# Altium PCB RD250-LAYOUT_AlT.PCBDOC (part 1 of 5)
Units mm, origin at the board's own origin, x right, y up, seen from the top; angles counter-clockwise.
Board outline 318.5 x 135 mm, 6 copper layers (TOP, Mid-Layer 1, Mid-Layer 2, Mid-Layer 3, Mid-Layer 4, BOTTOM), stack 1.422 mm thick; 550 components, 251 nets, 1350 pads, 626 vias.
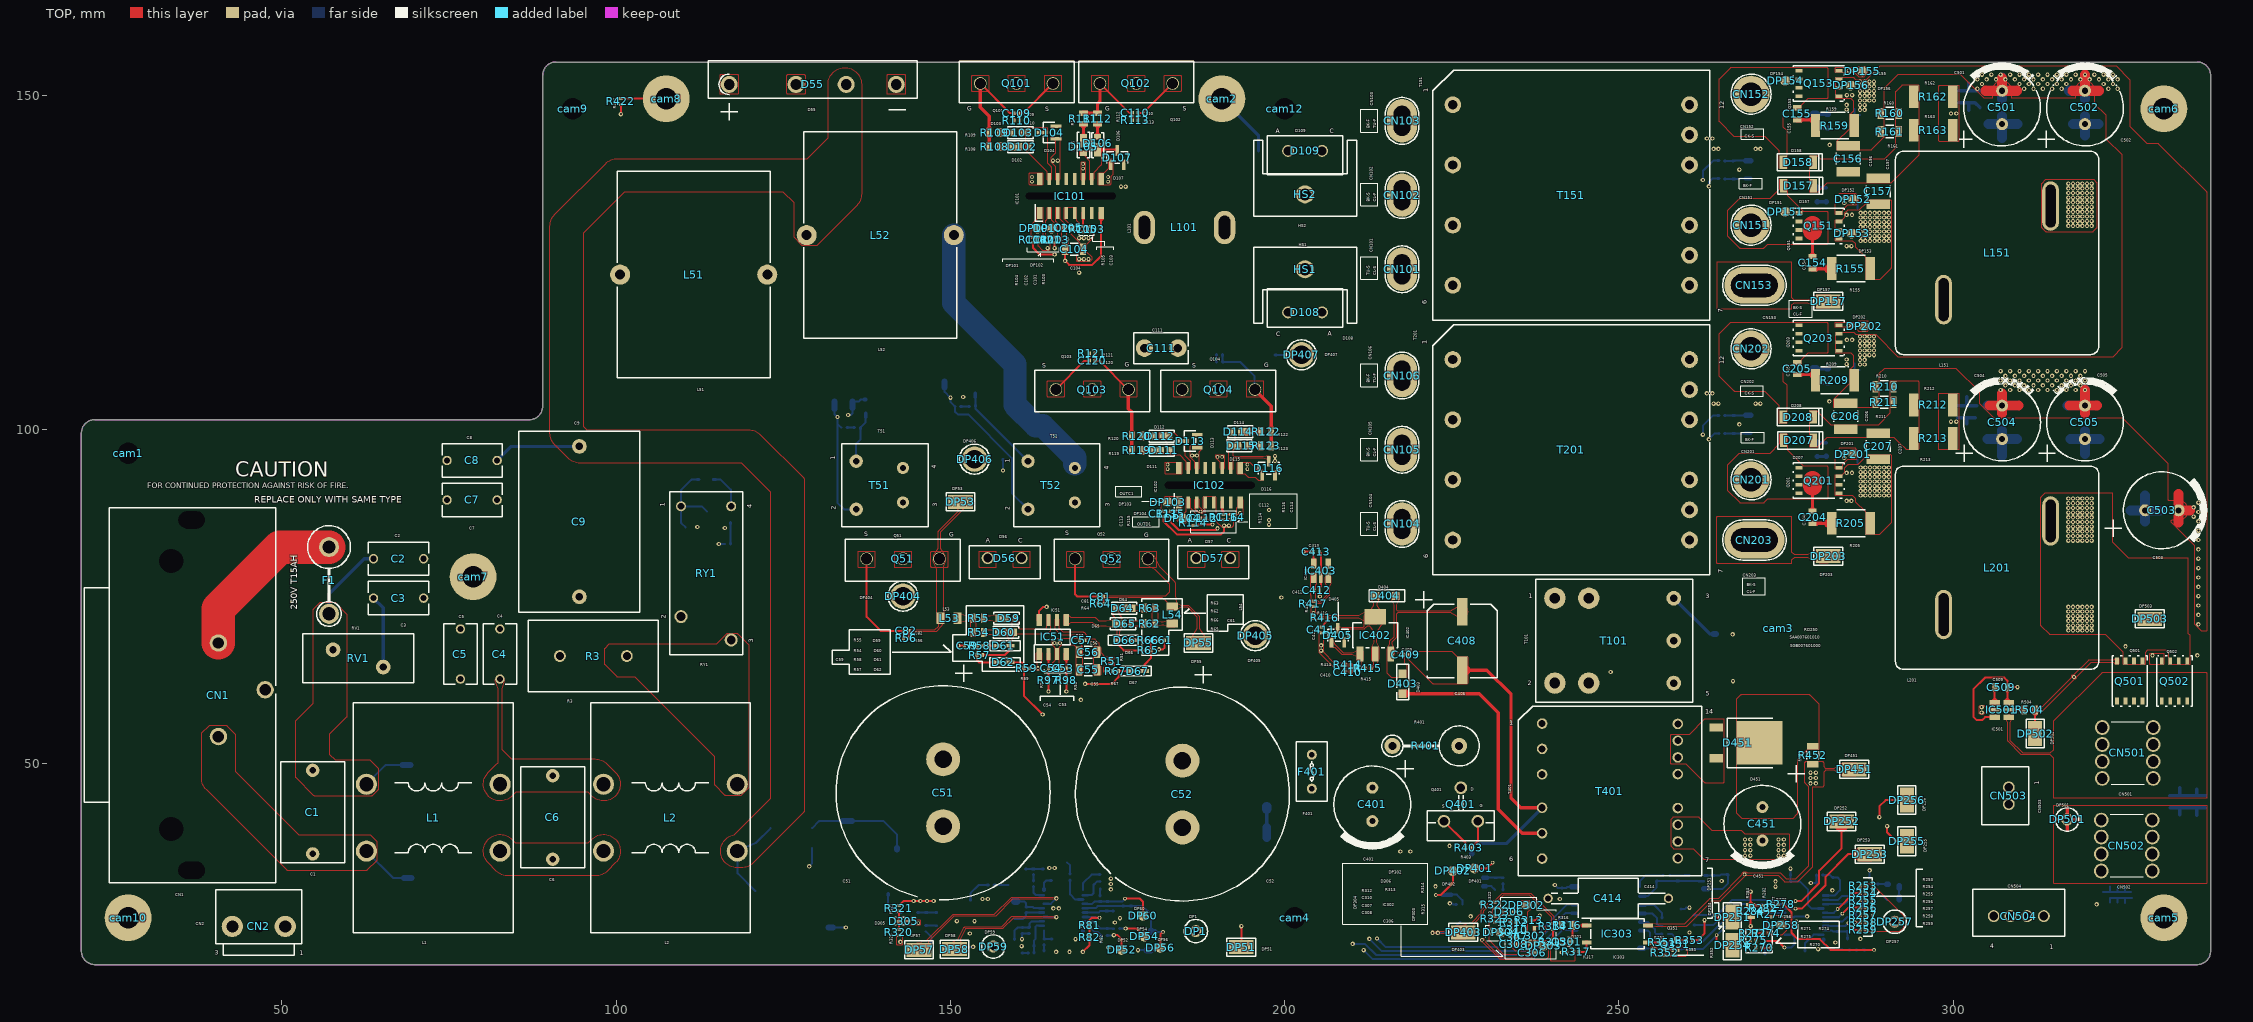
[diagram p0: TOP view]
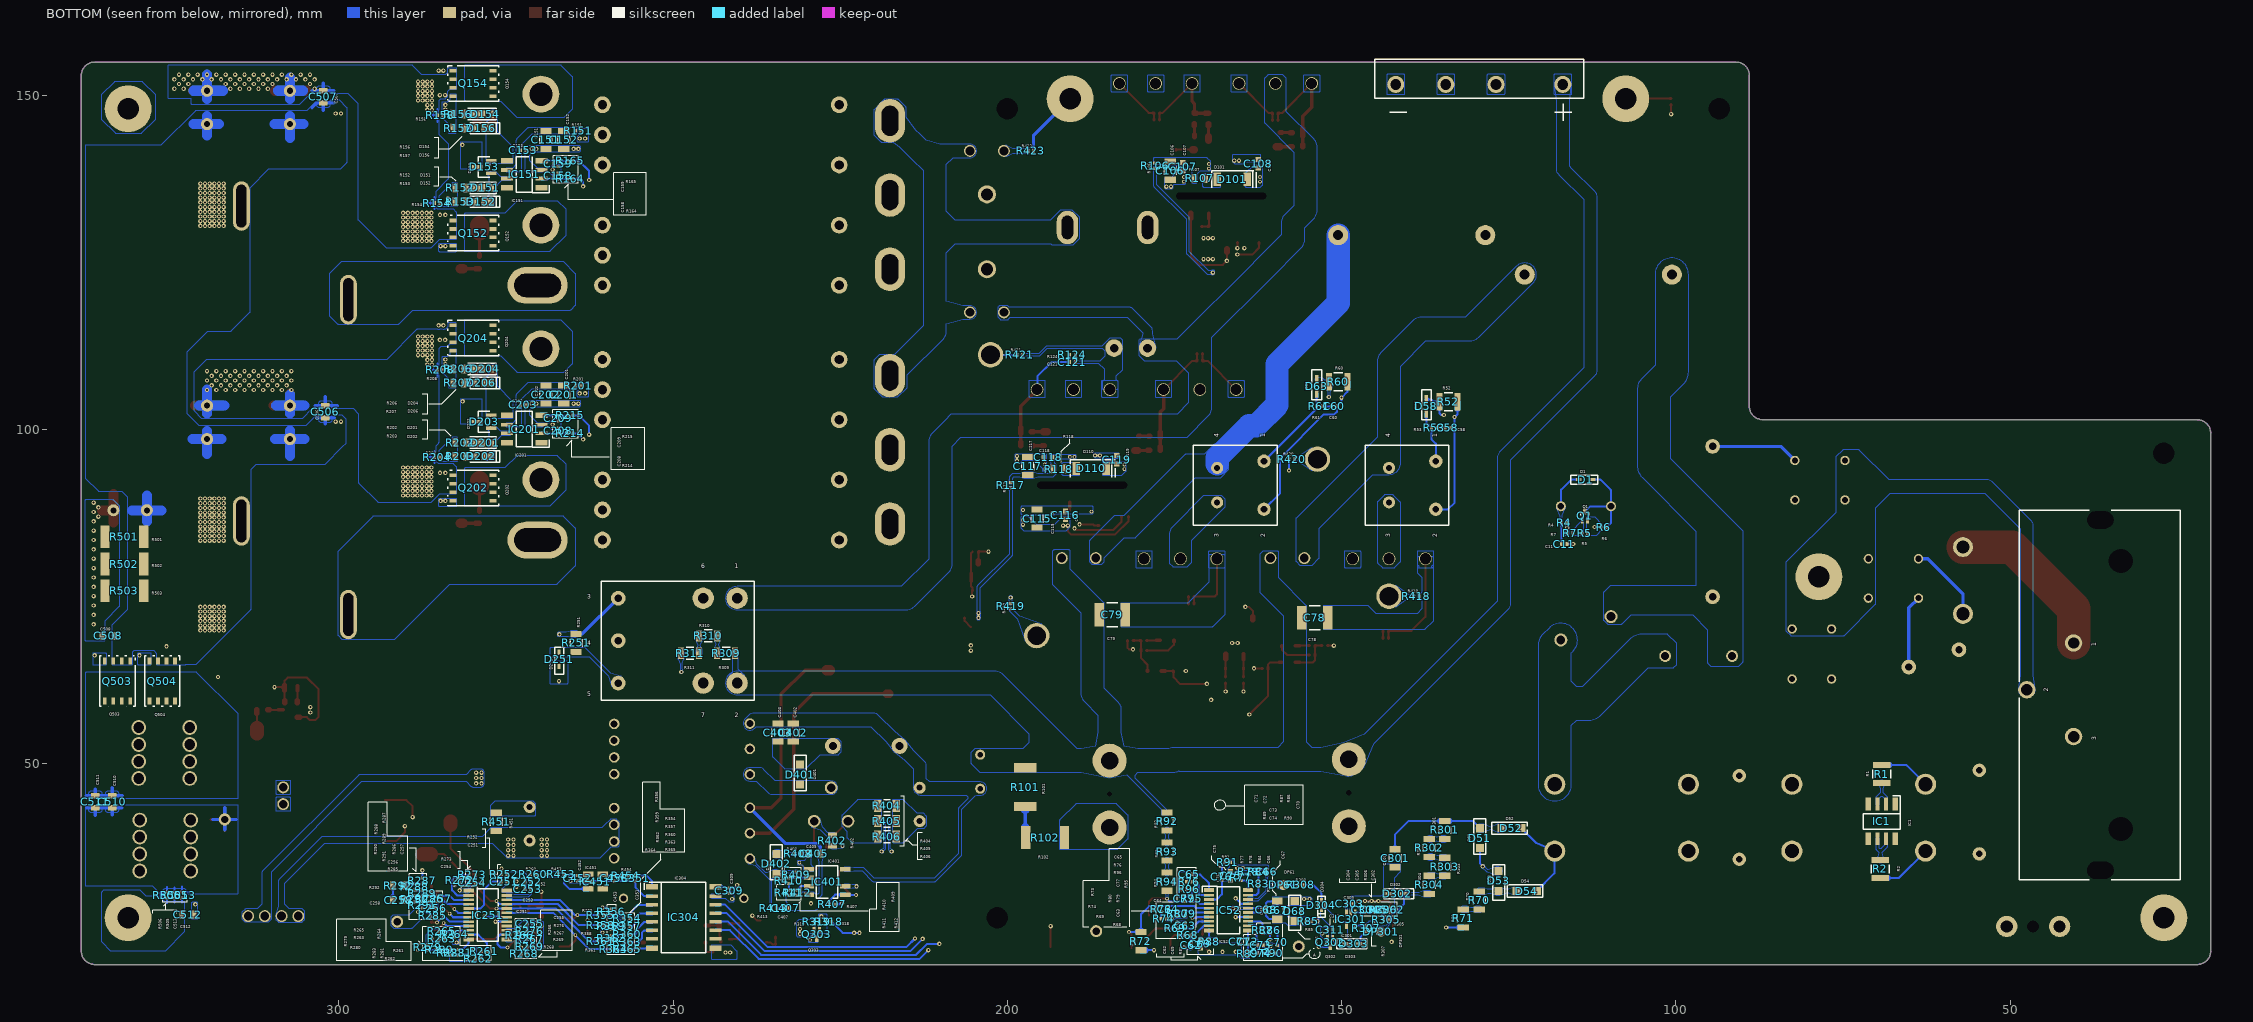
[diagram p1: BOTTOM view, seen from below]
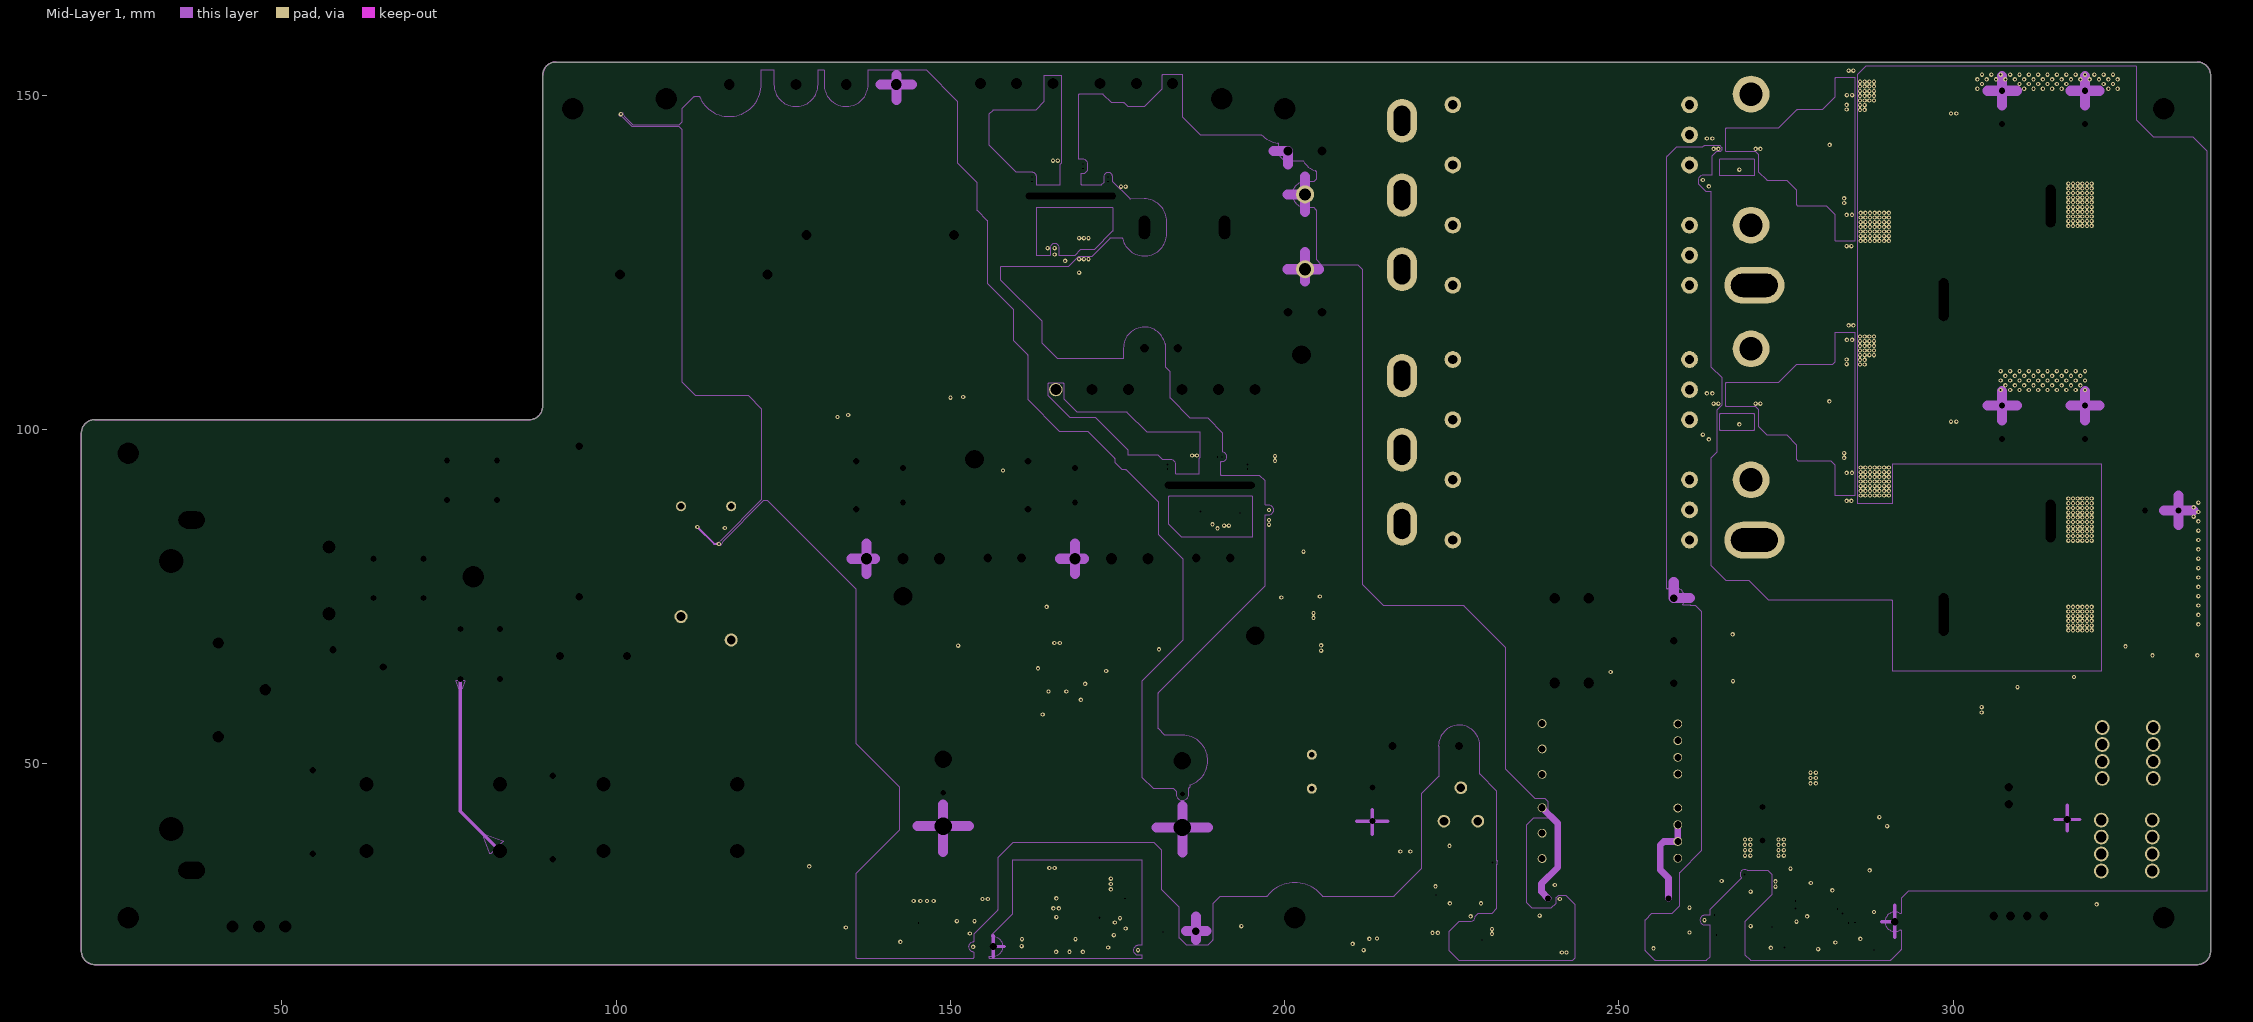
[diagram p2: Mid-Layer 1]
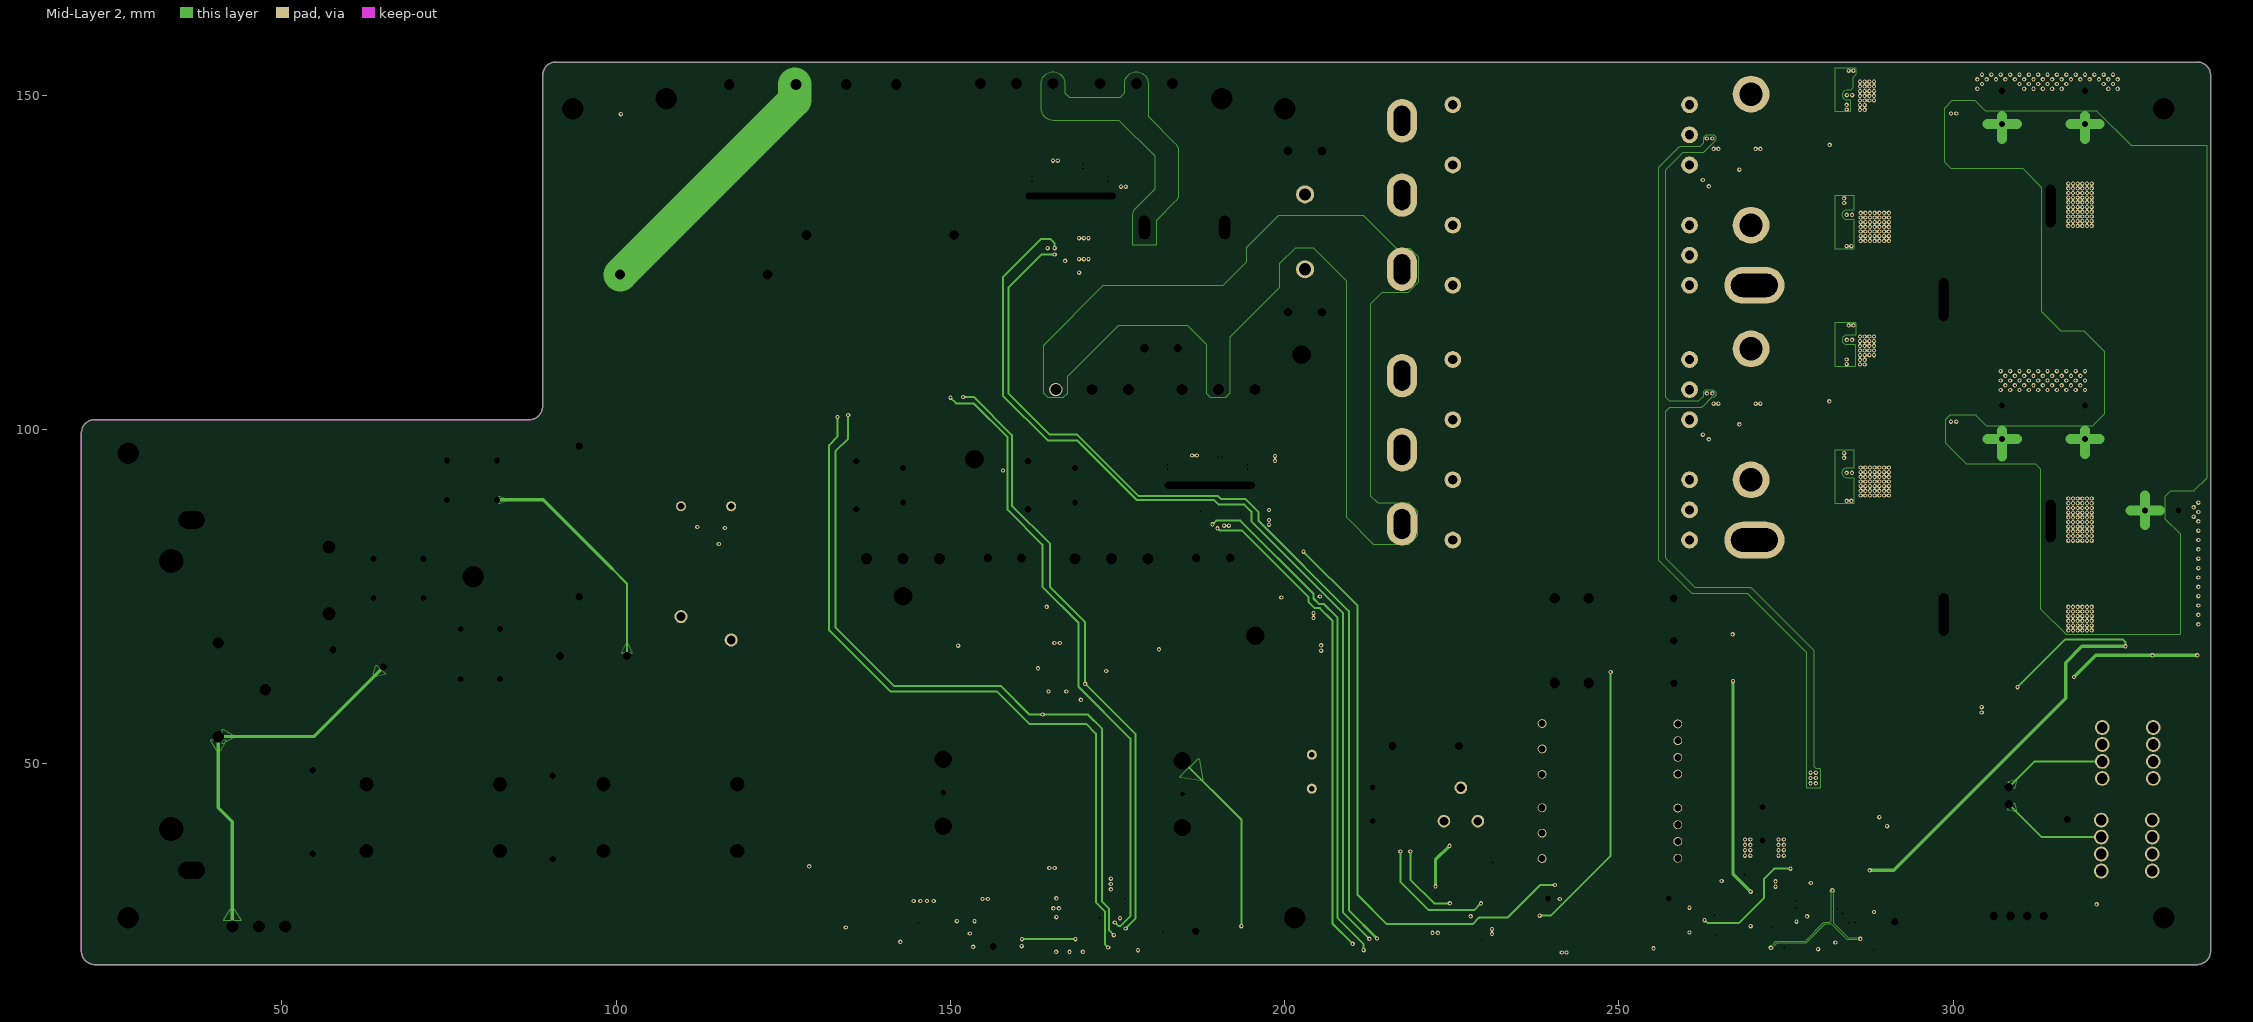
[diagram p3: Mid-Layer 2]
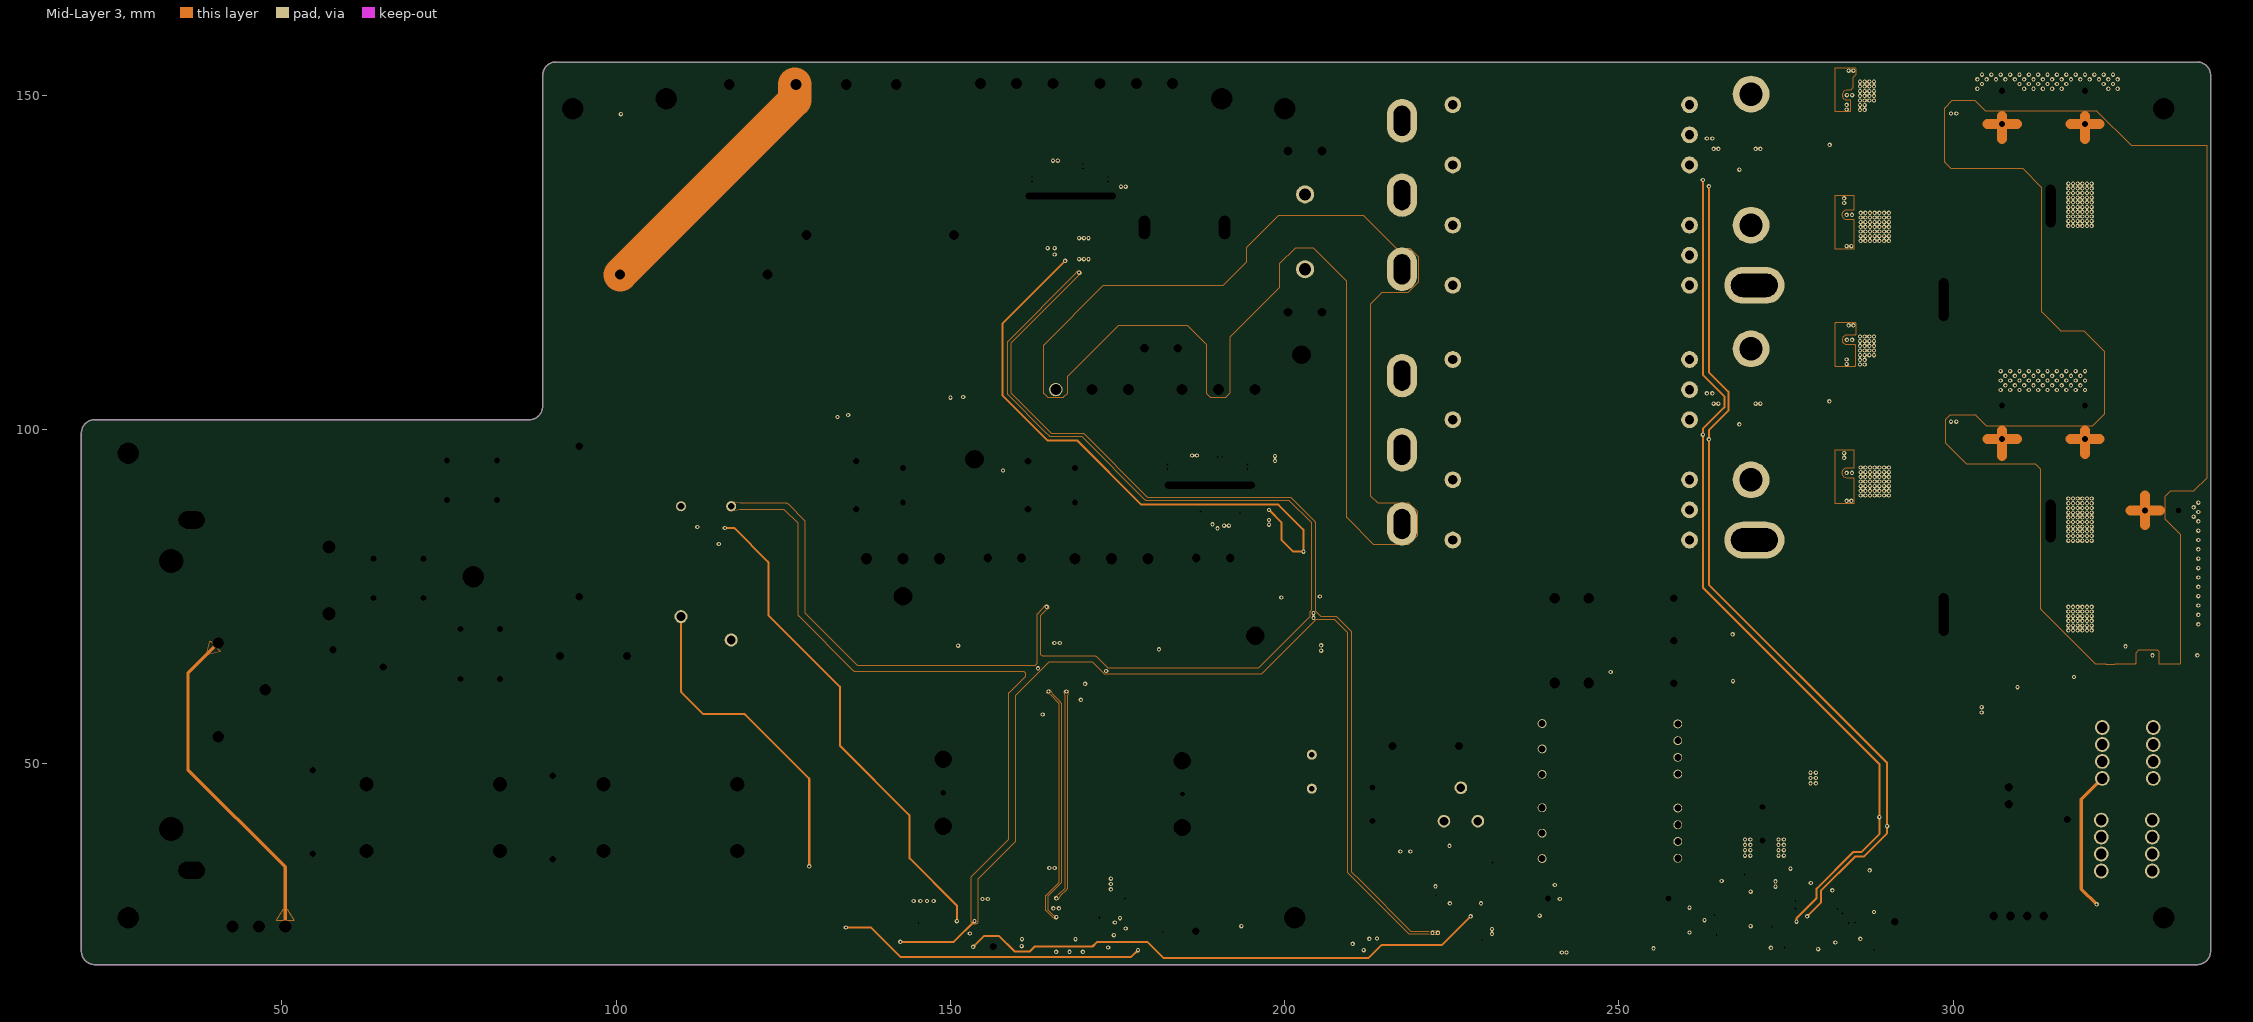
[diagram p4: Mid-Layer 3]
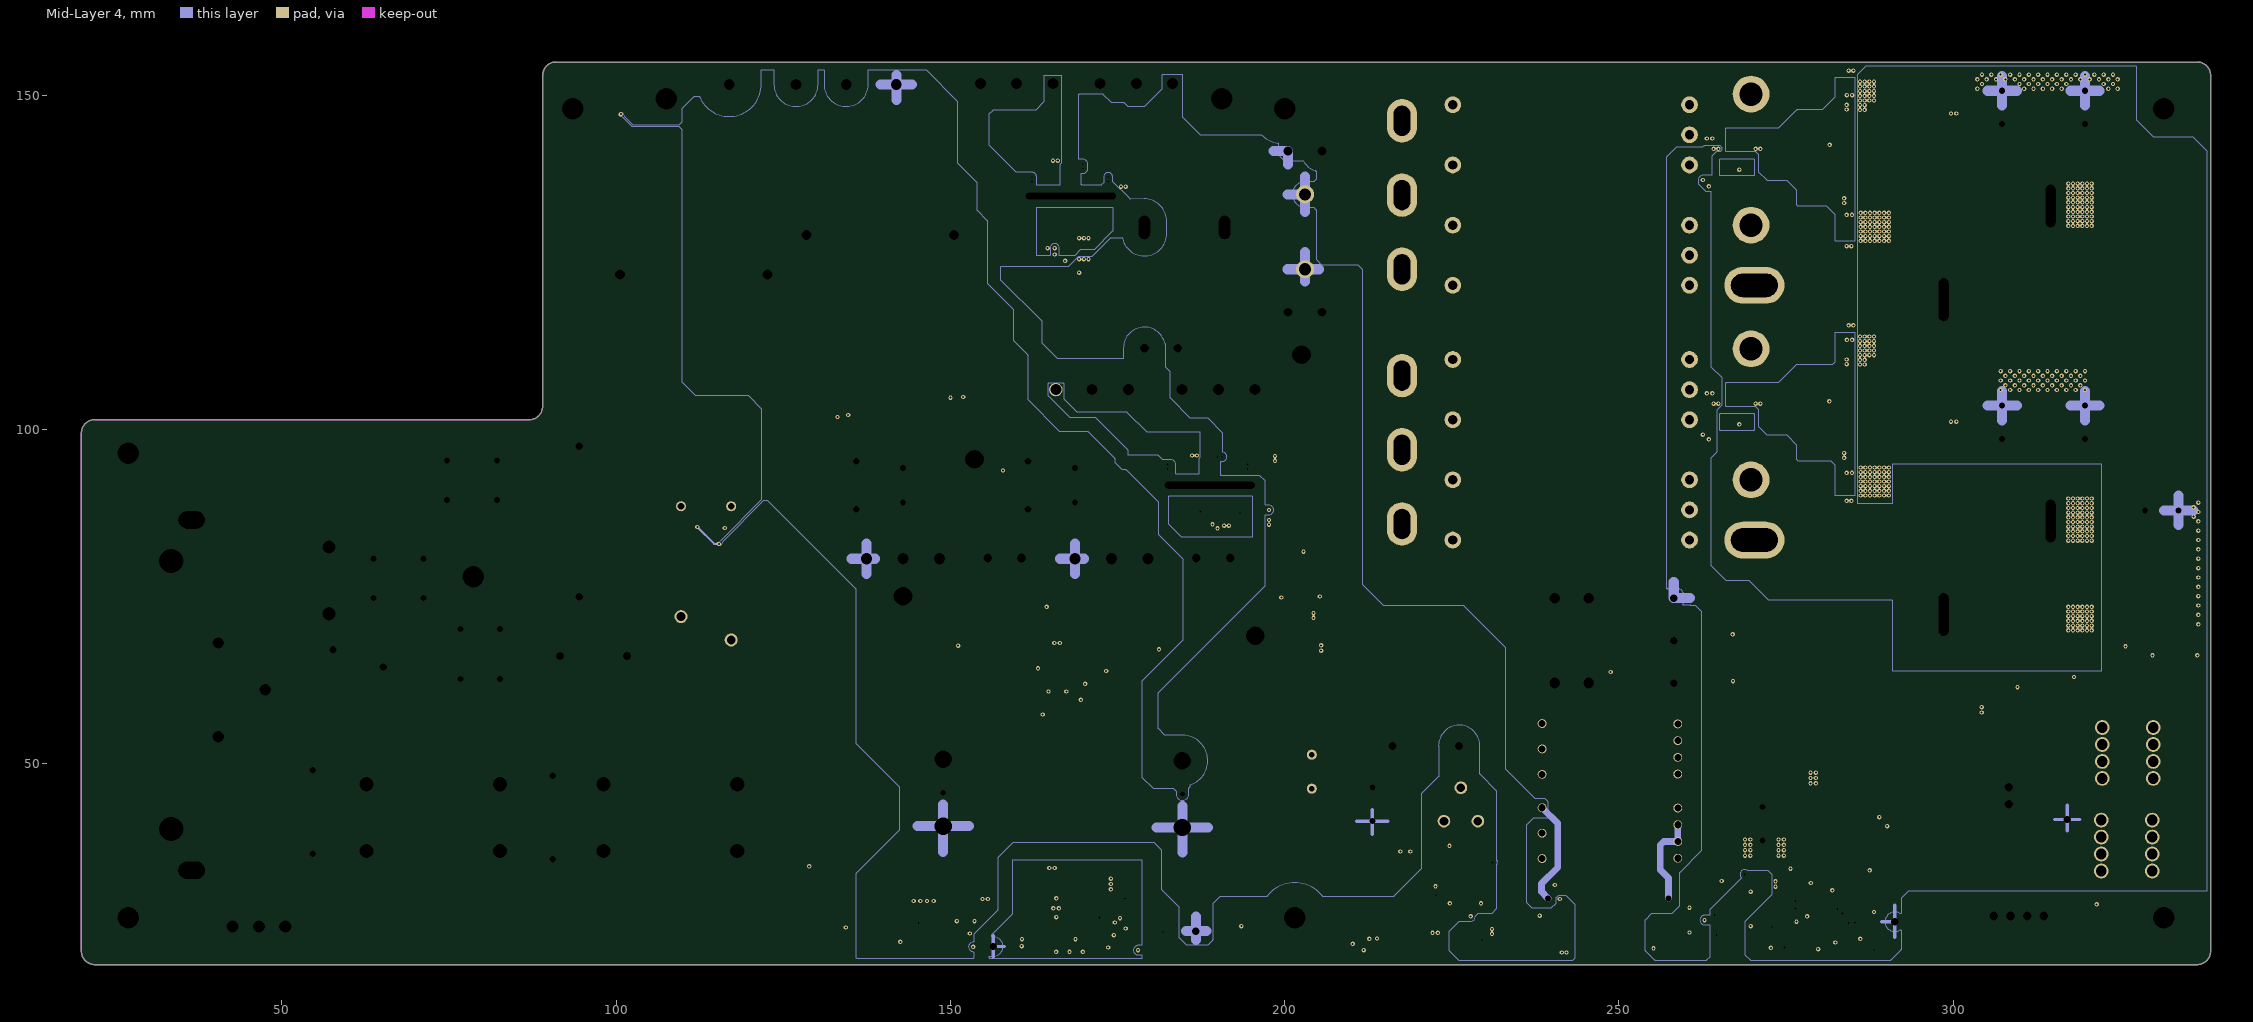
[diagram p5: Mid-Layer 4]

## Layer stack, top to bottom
Top Solder: solder mask 0.0102, Solder Resist, Dk 3.5
TOP: signal copper (thickness not stored)
Mid-Layer 1: signal copper 0.0356
Dielectric2: dielectric 0.32, FR-4, Dk 4.8
Mid-Layer 2: signal copper 0.0356
Dielectric3: dielectric 0.32, FR-4, Dk 4.8
Mid-Layer 3: signal copper 0.0356
Dielectric4: dielectric 0.32, FR-4, Dk 4.8
Mid-Layer 4: signal copper 0.0356
Dielectric5: dielectric 0.32, FR-4, Dk 4.8
BOTTOM: signal copper (thickness not stored)
Bottom Solder: solder mask 0.0102, Solder Resist, Dk 3.5

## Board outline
22,20 cw(c22,22) 20,22 20,99.5 cw(c22,99.5) 22,101.5 87,101.5 ccw(c87,103.5) 89,103.5 89,153 cw(c91,153) 91,155 336.5,155 cw(c336.5,153) 338.5,153 338.5,22 cw(c336.5,22) 336.5,20

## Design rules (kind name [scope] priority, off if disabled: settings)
AssemblyTestPointUsage [All] p0: scope1count=1 scope1_0_kind=Board scope1_0_value=Board scope2count=1 scope2_0_kind=Board scope2_0_value=Board commentlength=0
AssemblyTestpoint [All] p0: scope1count=1 scope1_0_kind=Board scope1_0_value=Board scope2count=1 scope2_0_kind=Board scope2_0_value=Board commentlength=0
Clearance [All] p0: scope1count=1 scope1_0_kind=Board scope1_0_value=Board scope2count=1 scope2_0_kind=Board scope2_0_value=Board commentlength=0 gap=0.3
Clearance [All] p1: gap=0.3 ignorepadtopadclearanceinfootprint=TRUE except(0.15: SMDPad-SMDPad THPad-THPad; 0.2: Arc-SMDPad Track-SMDPad SMDPad-Text; 0.25: SMDPad-Via; 0.425: Via-Via; 0.5: Arc-THPad Arc-Hole Track-THPad Track-Hole THPad-Fill THPad-Poly THPad-Region THPad-Text Fill-Hole Poly-Hole Region-Hole Text-Hole; 1: SMDPad-Hole THPad-Hole; 1.75: THPad-Via Via-Hole; 3: SMDPad-THPad)
ComponentClearance [All] p0: scope1count=1 scope1_0_kind=Board scope1_0_value=Board scope2count=1 scope2_0_kind=Board scope2_0_value=Board commentlength=0 gap=0.254 collisioncheckmode=3
DiffPairsRouting [All] p0: scope1count=1 scope1_0_kind=Board scope1_0_value=Board scope2count=1 scope2_0_kind=Board scope2_0_value=Board commentlength=0
FabricationTestPointUsage [All] p0: scope1count=1 scope1_0_kind=Board scope1_0_value=Board scope2count=1 scope2_0_kind=Board scope2_0_value=Board commentlength=0 valid=0 allowmultiple=FALSE
FabricationTestpoint [All] p0: scope1count=1 scope1_0_kind=Board scope1_0_value=Board scope2count=1 scope2_0_kind=Board scope2_0_value=Board commentlength=0 side=3 testpointundercomponent=TRUE minsize=1.016 maxsize=2.54 preferedsize=1.524 minholesize=0 maxholesize=1.016 preferedholesize=0.813 testpointgrid=0.025
FanoutControl Fanout_Default [All] p0: scope1count=1 scope1_0_kind=Board scope1_0_value=Board scope2count=1 scope2_0_kind=Board scope2_0_value=Board commentlength=30 // Fanout_Default (Default Rule)
FanoutControl Fanout_Small [All] p0 off: scope1count=1 scope1_0_kind=Board scope1_0_value=Board scope2count=1 scope2_0_kind=Board scope2_0_value=Board commentlength=84 // Protel DXP Scope 1 Expression Was: (CompPinCount < 5)   Fanout_Small (Default Rule)
FanoutControl Fanout_SOIC [All] p0 off: scope1count=1 scope1_0_kind=Board scope1_0_value=Board scope2count=1 scope2_0_kind=Board scope2_0_value=Board commentlength=71 // Protel DXP Scope 1 Expression Was: IsSOIC   Fanout_SOIC (Default Rule)
FanoutControl Fanout_LCC [All] p0 off: scope1count=1 scope1_0_kind=Board scope1_0_value=Board scope2count=1 scope2_0_kind=Board scope2_0_value=Board commentlength=69 // Protel DXP Scope 1 Expression Was: IsLCC   Fanout_LCC (Default Rule)
FanoutControl Fanout_BGA [All] p0 off: scope1count=1 scope1_0_kind=Board scope1_0_value=Board scope2count=1 scope2_0_kind=Board scope2_0_value=Board commentlength=69 // Protel DXP Scope 1 Expression Was: IsBGA   Fanout_BGA (Default Rule)
Height [All] p0: scope1count=1 scope1_0_kind=Board scope1_0_value=Board scope2count=1 scope2_0_kind=Board scope2_0_value=Board commentlength=0
HoleSize [All] p0: scope1count=1 scope1_0_kind=Board scope1_0_value=Board scope2count=1 scope2_0_kind=Board scope2_0_value=Board commentlength=0 absolutevalues=TRUE maxlimit=100 minlimit=0.001 maxpercent=80.000 minpercent=20.000
HoleSize [All] p1: absolutevalues=TRUE maxlimit=100 minlimit=0.001 maxpercent=80.000 minpercent=20.000
HoleToHoleClearance [All] p0: scope1count=1 scope1_0_kind=Board scope1_0_value=Board scope2count=1 scope2_0_kind=Board scope2_0_value=Board commentlength=0
HoleToHoleClearance [All] p1: gap=0.45 allowstackedmicrovias=FALSE
LayerPairs [All] p0: scope1count=1 scope1_0_kind=Board scope1_0_value=Board scope2count=1 scope2_0_kind=Board scope2_0_value=Board commentlength=0 enforce=TRUE
MinimumSolderMaskSliver [All] p0: scope1count=1 scope1_0_kind=Board scope1_0_value=Board scope2count=1 scope2_0_kind=Board scope2_0_value=Board commentlength=0
MinimumSolderMaskSliver [All] p1: minsoldermaskwidth=0.1
NetAntennae [All] p0: scope1count=1 scope1_0_kind=Board scope1_0_value=Board scope2count=1 scope2_0_kind=Board scope2_0_value=Board commentlength=0
NetAntennae [All] p1: netantennaetolerance=100
PasteMaskExpansion [All] p0: scope1count=1 scope1_0_kind=Board scope1_0_value=Board scope2count=1 scope2_0_kind=Board scope2_0_value=Board commentlength=0 expansion=0
PlaneClearance [All] p0: scope1count=1 scope1_0_kind=Board scope1_0_value=Board scope2count=1 scope2_0_kind=Board scope2_0_value=Board commentlength=0 clearance=0.001
PlaneClearance [All] p1: clearance=0.001
PlaneConnect [All] p0: scope1count=1 scope1_0_kind=Board scope1_0_value=Board scope2count=1 scope2_0_kind=Board scope2_0_value=Board commentlength=0 planeconnectstyle=Direct reliefexpansion=0.508 reliefentries=4 reliefconductorwidth=0.254 reliefairgap=0.254
PlaneConnect [All] p1: planeconnectstyle=Direct reliefexpansion=0.508 reliefentries=4 reliefconductorwidth=0.254 reliefairgap=0.254
PolygonConnect [All] p0: scope1count=1 scope1_0_kind=Board scope1_0_value=Board scope2count=1 scope2_0_kind=Board scope2_0_value=Board commentlength=0 connectstyle=Direct reliefconductorwidth=0.254 reliefentries=4 polygonreliefangle="90 Angle"
PolygonConnect [All] p1: connectstyle=Direct reliefconductorwidth=0.254 reliefentries=4 polygonreliefangle="90 Angle" airgapwidth=0.254
RoutingCorners [All] p0: scope1count=1 scope1_0_kind=Board scope1_0_value=Board scope2count=1 scope2_0_kind=Board scope2_0_value=Board commentlength=0 cornerstyle=45-Degree minsetback=2.54 maxsetback=2.54
RoutingLayers [All] p0: scope1count=1 scope1_0_kind=Board scope1_0_value=Board scope2count=1 scope2_0_kind=Board scope2_0_value=Board commentlength=0 top layer=Automatic mid layer 1=Automatic mid layer 2=Automatic mid layer 3=Automatic mid layer 4=Automatic bottom layer=Automatic
RoutingPriority [All] p0: scope1count=1 scope1_0_kind=Board scope1_0_value=Board scope2count=1 scope2_0_kind=Board scope2_0_value=Board commentlength=0
RoutingTopology [All] p0: scope1count=1 scope1_0_kind=Board scope1_0_value=Board scope2count=1 scope2_0_kind=Board scope2_0_value=Board commentlength=0 topology=Shortest
RoutingVias [All] p0: scope1count=1 scope1_0_kind=Board scope1_0_value=Board scope2count=1 scope2_0_kind=Board scope2_0_value=Board commentlength=0 holewidth=0.1 width=0.1 viastyle="Through Hole" minholewidth=0.001 minwidth=0.001 maxholewidth=100 maxwidth=100
RoutingVias [All] p1: holewidth=0.1 width=0.1 viastyle="Through Hole" minholewidth=0.001 minwidth=0.001 maxholewidth=100 maxwidth=100
ShortCircuit [All] p0: scope1count=1 scope1_0_kind=Board scope1_0_value=Board scope2count=1 scope2_0_kind=Board scope2_0_value=Board commentlength=0 allowed=FALSE
SilkToBoardRegionClearance [All] p0: scope1count=1 scope1_0_kind=Board scope1_0_value=Board scope2count=1 scope2_0_kind=Board scope2_0_value=Board commentlength=0
SilkToSilkClearance [All] p0: scope1count=1 scope1_0_kind=Board scope1_0_value=Board scope2count=1 scope2_0_kind=Board scope2_0_value=Board commentlength=0
SilkToSilkClearance [All] p1: silktosilkclearance=0.001
SilkToSolderMaskClearance [All] p0 off: scope1count=1 scope1_0_kind=Board scope1_0_value=Board scope2count=1 scope2_0_kind=Board scope2_0_value=Board commentlength=44 // Protel DXP Scope 1 Expression Was: IsPad
SilkToSolderMaskClearance [IsPad] p1: minsilkscreentomaskgap=0.11 clearancetoexposedcopper=TRUE
SolderMaskExpansion [All] p0: scope1count=1 scope1_0_kind=Board scope1_0_value=Board scope2count=1 scope2_0_kind=Board scope2_0_value=Board commentlength=0 expansion=0.001
SolderMaskExpansion [All] p1: expansion=0.001
UnRoutedNet [All] p0: scope1count=1 scope1_0_kind=Board scope1_0_value=Board scope2count=1 scope2_0_kind=Board scope2_0_value=Board commentlength=0
UnpouredPolygon [All] p0: scope1count=1 scope1_0_kind=Board scope1_0_value=Board scope2count=1 scope2_0_kind=Board scope2_0_value=Board commentlength=0
Width [All] p0: scope1count=1 scope1_0_kind=Board scope1_0_value=Board scope2count=1 scope2_0_kind=Board scope2_0_value=Board commentlength=0 maxlimit=1000 minlimit=2539.975 preferedwidth=0
Width [All] p1: maxlimit=1000 minlimit=2539.975 preferedwidth=0 toplayer_minwidth=0 midlayer1_minwidth=0 midlayer2_minwidth=0 midlayer3_minwidth=0 midlayer4_minwidth=0 bottomlayer_minwidth=0 minimp=50.000000 maximp=50.000000 favimp=50.000000
22 further rules are at their usual default settings.

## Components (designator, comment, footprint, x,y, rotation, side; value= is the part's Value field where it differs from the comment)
C1 "FTP_73" FTP_73 54.6,42.8 r90 top
C2 "Local_DE2E3SA222MN3AT02F" Local_DE2E3SA222MN3AT02F 71.2,80.7 r180 top
C3 "Local_DE2E3SA222MN3AT02F" Local_DE2E3SA222MN3AT02F 71.2,74.8 r180 top
C4 "Local_DE2E3SA222MN3AT02F" Local_DE2E3SA222MN3AT02F 82.6,70.2 r270 top
C5 "Local_DE2E3SA222MN3AT02F" Local_DE2E3SA222MN3AT02F 76.7,70.2 r270 top
C6 "FTP_73" FTP_73 90.5,42 r90 top
C7 "Local_DE2E3SA222MN3AT02F" Local_DE2E3SA222MN3AT02F 74.7,89.5 r0 top
C8 "Local_DE2E3SA222MN3AT02F" Local_DE2E3SA222MN3AT02F 74.7,95.4 r0 top
C9 "FTP_75" FTP_75 94.5,86.25 r270 top
C11 "FTP_66" FTP_66 116.7,82.9 r0 bottom
C51 "Local_AL-CAP-f30-A" Local_AL-CAP-f30-A 148.9,45.7 r90 top
C52 "Local_AL-CAP-f30-A" Local_AL-CAP-f30-A 184.7,45.5 r90 top
C53 "FTP_65" FTP_65 166.9,64.3 r0 top
C54 "FTP_65" FTP_65 165.1,64.3 r180 top
C55 "FTP_15" FTP_15 170.6,64.1 r0 top
C56 "FTP_15" FTP_15 170.6,66.7 r0 top
C57 "FTP_65" FTP_65 169.7,68.5 r0 top
C58 "FTP_66" FTP_66 134.1,100.3 r0 bottom
C59 "FTP_65" FTP_65 152.5,67.7 r0 top
C60 "FTP_66" FTP_66 151.1,103.5 r0 bottom
C61 "FTP_65" FTP_65 181.6,68.5 r180 top
C62 "FTP_66" FTP_66 172.5,22.9 r90 bottom
C63 "FTP_66" FTP_66 173.4,25.8 r270 bottom
C64 "FTP_66" FTP_66 175.9,28.3 r90 bottom
C65 "FTP_66" FTP_66 172.8,33.5 r180 bottom
C66 "FTP_66" FTP_66 161.2,33.9 r270 bottom
C67 "FTP_25" FTP_25 159.6,28.15 r270 bottom
C68 "FTP_66" FTP_66 161.3,28.2 r270 bottom
C69 "FTP_68" FTP_68 171.1,23.1 r90 bottom
C70 "FTP_66" FTP_66 159.6,23.3 r90 bottom
C71 "FTP_66" FTP_66 165.2,23.4 r90 bottom
C72 "FTP_66" FTP_66 164,23.4 r90 bottom
C73 "FTP_66" FTP_66 162.1,22.9 r0 bottom
C74 "FTP_66" FTP_66 162.1,21.7 r0 bottom
C75 "FTP_68" FTP_68 166.6,33.3 r270 bottom
C76 "FTP_66" FTP_66 167.9,33.1 r270 bottom
C77 "FTP_66" FTP_66 173.5,29.85 r270 bottom
C78 "DC835R1BKP" DC835R1BKP 154,71.9 r0 bottom
C79 "DC835R1BKP" DC835R1BKP 184.3,72.3 r0 bottom
C81 "FTP_65" FTP_65 172.5,75.05 r0 top
C82 "FTP_65" FTP_65 143.4,69.9 r0 top
C101 "FTP_65" FTP_65 164.55,128.4 r90 top
C102 "FTP_65" FTP_65 163.45,128.4 r90 top
C103 "FTP_65" FTP_65 170.95,130 r90 top
C104 "FTP_15" FTP_15 168.5,127 r180 top
C105 "KC01670AKP" KC01670AKP 167.65,130.2 r180 top
C106 "FTP_16" FTP_16 175.65,138.75 r270 bottom
C107 "KC01670BKP" KC01670BKP 173.75,139.35 r90 bottom
C108 "KC01670BKP" KC01670BKP 162.45,139.8 r270 bottom
C109 "FTP_65" FTP_65 159.9,147.35 r180 top
C110 "FTP_65" FTP_65 177.65,147.4 r180 top
C111 "Local_RDER73A104K5B1H03B-A" Local_RDER73A104K5B1H03B-A 184,112.2 r180 top
C112 "FTP_65" FTP_65 187.8,86.75 r180 top
C113 "FTP_65" FTP_65 181.85,87.45 r90 top
C114 "FTP_65" FTP_65 191.95,86.9 r90 top
C115 "FTP_16" FTP_16 195.55,86.7 r270 bottom
C116 "KC01670BKP" KC01670BKP 191.3,87.2 r90 bottom
C117 "FTP_16" FTP_16 196.95,94.55 r90 bottom
C118 "KC01670BKP" KC01670BKP 193.9,95.85 r180 bottom
C119 "KC01670BKP" KC01670BKP 183.65,95.5 r270 bottom
C120 "FTP_65" FTP_65 171.2,110.3 r0 top
C121 "FTP_66" FTP_66 190.25,110.125 r0 bottom
C151 "FTP_16" FTP_16 269,143.35 r270 bottom
C152 "FTP_16" FTP_16 266.35,143.35 r270 bottom
C153 "FTP_66" FTP_66 272.4,141.8 r0 bottom
C154 "KC00060AKP" KC00060AKP 278.95,125 r90 top
C155 "KC00060AKP" KC00060AKP 276.65,147.25 r90 top
C156 "DC835R1AKP" DC835R1AKP 284.3,140.55 r270 top
C157 "DC835R1AKP" DC835R1AKP 288.8,135.65 r90 top
C158 "FTP_66" FTP_66 267.15,137.95 r270 bottom
C159 "FTP_66" FTP_66 267.15,139.8 r90 bottom
C201 "FTP_16" FTP_16 266.35,105.25 r270 bottom
C202 "FTP_16" FTP_16 269,105.25 r270 bottom
C203 "FTP_66" FTP_66 272.4,103.7 r0 bottom
C204 "KC00060AKP" KC00060AKP 278.95,86.9 r90 top
C205 "KC00060AKP" KC00060AKP 276.65,109.15 r90 top
C206 "DC835R1AKP" DC835R1AKP 283.9,102 r270 top
C207 "DC835R1AKP" DC835R1AKP 288.8,97.55 r90 top
C208 "FTP_66" FTP_66 267.15,99.85 r270 bottom
C209 "FTP_66" FTP_66 267.15,101.7 r90 bottom
C251 "FTP_66" FTP_66 275.225,32.4 r0 bottom
C252 "FTP_66" FTP_66 271.7,32.4 r180 bottom
C253 "FTP_66" FTP_66 271.7,31.3 r180 bottom
C254 "FTP_66" FTP_66 280,32.2 r0 bottom
C255 "FTP_66" FTP_66 271.4,26.1 r0 bottom
C256 "FTP_66" FTP_66 285.9,28.4 r180 bottom
C257 "FTP_66" FTP_66 285.2,29.85 r270 bottom
C258 "KC00060BKP" KC00060BKP 291,29.65 r0 bottom
C301 "FTP_16" FTP_16 142,35.9 r270 bottom
C302 "FTP_66" FTP_66 142.7,28.2 r270 bottom
C303 "FTP_66" FTP_66 148.8,29.1 r0 bottom
C304 "FTP_66" FTP_66 146.4,28.2 r270 bottom
C305 "FTP_66" FTP_66 145.1,28.2 r270 bottom
C306 "FTP_65" FTP_65 237,21.8 r0 top
C307 "FTP_65" FTP_65 234.25,24.1 r0 top
C308 "FTP_65" FTP_65 234.25,23 r0 top
C309 "FTP_66" FTP_66 241.55,31.05 r90 bottom
C310 "FTP_65" FTP_65 234.25,25.2 r0 top
C311 "FTP_66" FTP_66 151.7,25.2 r180 bottom
C351 "FTP_66" FTP_66 255.6,32.9 r90 bottom
C401 "FTP_13" FTP_13 213.1,41.45 r90 top
C402 "FTP_16" FTP_16 232,54.7 r270 bottom
C403 "FTP_16" FTP_16 234.3,54.7 r270 bottom
C405 "KC00060BKP" KC00060BKP 228.85,36.55 r0 bottom
C407 "FTP_66" FTP_66 233.15,28.45 r0 bottom
C408 "DC845R0AKP" DC845R0AKP 226.55,68.4 r90 top
C409 "FTP_65" FTP_65 218.1,66.35 r180 top
C410 "FTP_65" FTP_65 209.45,63.75 r0 top
C411 "FTP_65" FTP_65 205.45,70.05 r90 top
C412 "FTP_65" FTP_65 204.8,75.95 r180 top
C413 "FTP_65" FTP_65 204.75,81.75 r180 top
C414 "SIK00180ATP_RD244-A" SIK00180ATP_RD244-A 244.65,29.9 r0 top
C451 "FTP_13" FTP_13 271.45,38.55 r90 top
C452 "FTP_66" FTP_66 264.255,32.9 r90 bottom
C453 "FTP_66" FTP_66 258.8,32.9 r90 bottom
C501 "FTP_13" FTP_13 307.3,150.7 r270 top
C502 "FTP_13" FTP_13 319.7,150.7 r270 top
C503 "FTP_13" FTP_13 333.7,87.95 r180 top
C504 "FTP_13" FTP_13 307.3,103.6 r270 top
C505 "FTP_13" FTP_13 319.7,103.6 r270 top
C506 "KC00060BKP" KC00060BKP 302,102.7 r270 bottom
C507 "KC00060BKP" KC00060BKP 302.3,149.8 r270 bottom
C508 "KC00060BKP" KC00060BKP 334.45,69.15 r180 bottom
C509 "KC00060AKP" KC00060AKP 307.2,61.5 r0 top
C510 "KC00060BKP" KC00060BKP 333.9,44.35 r90 bottom
C511 "KC00060BKP" KC00060BKP 336.4,44.35 r90 bottom
C512 "KC00060BKP" KC00060BKP 322.55,27.45 r180 bottom
C513 "FTP_66" FTP_66 323.45,30.4 r270 bottom
cam1 "NTC320" NTC320 27,96.5 r0 top
cam2 "FTP_114" FTP_114 190.6,149.5 r0 top
cam3 "UTOS12" UTOS12 273.8,70.3 r0 top
cam4 "NTC320" NTC320 201.5,27 r0 top
cam5 "FTP_114" FTP_114 331.5,27 r0 top
cam6 "FTP_114" FTP_114 331.5,148 r0 top
cam7 "T3.2_7.0" T3.2_7.0 78.6,78 r0 top
cam8 "FTP_114" FTP_114 107.5,149.5 r0 top
cam9 "NTC320" NTC320 93.5,148 r0 top
cam10 "FTP_114" FTP_114 27,27 r0 top
cam12 "NTC320" NTC320 200,148 r0 top
CN1 "FTP_9" FTP_9 24.7,60.3 r270 top
CN2 "DJA415" DJA415 50.5,25.7 r180 top
CN101 "Local_LONGHOLE_250-450" Local_LONGHOLE_250-450 217.55,124 r270 top
CN102 "Local_LONGHOLE_250-450" Local_LONGHOLE_250-450 217.55,135.1 r90 top
CN103 "Local_LONGHOLE_250-450" Local_LONGHOLE_250-450 217.55,146.2 r90 top
CN104 "Local_LONGHOLE_250-450" Local_LONGHOLE_250-450 217.55,85.9 r90 top
CN105 "Local_LONGHOLE_250-450" Local_LONGHOLE_250-450 217.55,97 r90 top
CN106 "Local_LONGHOLE_250-450" Local_LONGHOLE_250-450 217.55,108.1 r90 top
CN151 "Local_TH350-P550" Local_TH350-P550 269.75,130.6 r0 top
CN152 "Local_TH350-P550" Local_TH350-P550 269.75,150.2 r0 top
CN153 "Local_LONGHOLE_350-700" Local_LONGHOLE_350-700 270.25,121.6 r0 top
CN201 "Local_TH350-P550" Local_TH350-P550 269.75,92.5 r0 top
CN202 "Local_TH350-P550" Local_TH350-P550 269.75,112.1 r0 top
CN203 "Local_LONGHOLE_350-700" Local_LONGHOLE_350-700 270.25,83.5 r0 top
CN501 "Local_7460305-A" Local_7460305-A 326.1,51.65 r270 top
CN502 "Local_7460305-A" Local_7460305-A 325.95,37.8 r270 top
CN503 "CUK02330ATP" CUK02330ATP 308.3,46.5 r270 top
CN504 "CUP10050ATP" CUP10050ATP 313.55,27.25 r180 top
D1 "FTP_32" FTP_32 113.45,92.55 r180 bottom
D51 "MMK01670BKP" MMK01670BKP 129.3,38.9 r270 bottom
D52 "MMK01670BKP" MMK01670BKP 124.6,40.4 r180 bottom
D53 "MMK01670BKP" MMK01670BKP 126.5,32.5 r90 bottom
D54 "MMK01670BKP" MMK01670BKP 122.3,31 r180 bottom
D55 "Local_GSIB2580-A" Local_GSIB2580-A 116.9,151.65 r0 top
D56 "Local_TO-220-2L-A" Local_TO-220-2L-A 155.56,80.8 r0 top
D57 "Local_TO-220-2L-A" Local_TO-220-2L-A 186.76,80.8 r0 top
D58 "FTP_22" FTP_22 137.31,103.5 r270 bottom
D59 "US2H_A" US2H_A 158.4,71.8 r0 top
D60 "US2H_A" US2H_A 158.3,69.7 r180 top
D61 "FTP_20" FTP_20 157.9,67.7 r0 top
D62 "FTP_20" FTP_20 157.9,65.2 r0 top
D63 "FTP_22" FTP_22 153.7,106.5 r270 bottom
D64 "US2H_A" US2H_A 176,73.3 r180 top
D65 "US2H_A" US2H_A 175.8,71 r0 top
D66 "FTP_20" FTP_20 176.1,68.5 r180 top
D67 "FTP_20" FTP_20 178,63.9 r180 top
D68 "FTP_86" FTP_86 157,28 r90 bottom
D101 "FTP_82" FTP_82 166.35,137.45 r0 bottom
D102 "US2H_A" US2H_A 160.45,142.35 r0 top
D103 "US2H_A" US2H_A 160.45,144.45 r180 top
D104 "FTP_27" FTP_27 164.75,144.45 r90 top
D105 "US2H_A" US2H_A 169.9,142.6 r270 top
D106 "US2H_A" US2H_A 172,142.55 r90 top
D107 "FTP_27" FTP_27 174.95,140.7 r0 top
D108 "DD504V" DD504V 205.58,117.55 r180 top
D109 "DD504V" DD504V 200.5,141.7 r0 top
D110 "FTP_82" FTP_82 187.45,94.2 r0 bottom
D111 "US2H_A" US2H_A 181.6,96.9 r0 top
D112 "US2H_A" US2H_A 181.6,99.05 r180 top
D113 "FTP_27" FTP_27 185.85,98.3 r90 top
D114 "US2H_A" US2H_A 193.35,99.7 r180 top
D115 "US2H_A" US2H_A 193.2,97.6 r0 top
D116 "FTP_27" FTP_27 197.6,94.25 r0 top
D151 "US2H_B" US2H_B 278.4,136.175 r0 bottom
D152 "US2H_B" US2H_B 278.4,134.1 r180 bottom
D153 "FTP_31" FTP_31 278.25,139.3 r270 bottom
D154 "US2H_B" US2H_B 278.4,147.2 r0 bottom
D156 "US2H_B" US2H_B 278.4,145.1 r180 bottom
D157 "FTP_81" FTP_81 276.85,136.5 r0 top
D158 "FTP_81" FTP_81 276.8,140 r0 top
D201 "US2H_B" US2H_B 278.4,98.075 r0 bottom
D202 "US2H_B" US2H_B 278.4,96 r180 bottom
D203 "FTP_31" FTP_31 278.25,101.2 r270 bottom
D204 "US2H_B" US2H_B 278.4,109.1 r0 bottom
D206 "US2H_B" US2H_B 278.4,107 r180 bottom
D207 "FTP_81" FTP_81 276.85,98.4 r0 top
D208 "FTP_81" FTP_81 276.8,101.9 r0 top
D251 "FTP_32" FTP_32 267.05,65.7 r90 bottom
D302 "D9K022" D9K022 141.7,30.6 r0 bottom
D303 "FTP_22" FTP_22 148.2,23.1 r180 bottom
D304 "D8101D1BKP" D8101D1BKP 153,28.9 r90 bottom
D305 "D8101D1AKP" D8101D1AKP 143,26.5 r0 top
D306 "D8101D1AKP" D8101D1AKP 233.6,27.9 r0 top
D401 "MMK01670BKP" MMK01670BKP 231,48.4 r270 bottom
D402 "MMK01670BKP" MMK01670BKP 234.55,35.05 r270 bottom
D403 "MMK01670AKP" MMK01670AKP 217.65,62 r90 top
D404 "MMK01670AKP" MMK01670AKP 215.05,75.15 r0 top
D405 "FTP_27" FTP_27 207.95,69.25 r0 top
D451 "DIC8V2" DIC8V2 269.6,53.15 r270 top
DP1 "FTP_71" FTP_71 186.7,25 r0 top
DP51 "FTP_57" FTP_57 193.5,22.6 r0 top
DP52 "DTP815" DTP815 175.6,22.2 r0 top
DP53 "FTP_57" FTP_57 151.5,89.2 r0 top
DP54 "DTP815" DTP815 179,24.2 r0 top
DP55 "FTP_57" FTP_57 187.1,68.1 r0 top
DP56 "DTP815" DTP815 181.4,22.5 r180 top
DP57 "FTP_57" FTP_57 145.3,22.2 r0 top
DP58 "FTP_57" FTP_57 150.6,22.3 r0 top
DP59 "FTP_71" FTP_71 156.4,22.7 r0 top
DP60 "DTP815" DTP815 178.8,27.3 r0 top
DP61 "DTP915" DTP915 158.7,31.9 r0 bottom
DP101 "DTP815" DTP815 163,130.1 r0 top
DP102 "DTP815" DTP815 165.1,130.1 r0 top
DP103 "DTP815" DTP815 182.5,89.15 r0 top
DP104 "DTP815" DTP815 184.7,86.75 r90 top
DP151 "DTP815" DTP815 274.85,132.6 r0 top
DP152 "DTP815" DTP815 285,134.45 r0 top
DP153 "DTP815" DTP815 284.8,129.35 r0 top
DP154 "DTP815" DTP815 274.85,152.2 r0 top
DP155 "DTP815" DTP815 286.4,153.6 r0 top
DP156 "DTP815" DTP815 284.65,151.5 r0 top
DP157 "FTP_57" FTP_57 281.3,119.2 r0 top
DP201 "DTP815" DTP815 285,96.35 r0 top
DP202 "DTP815" DTP815 286.65,115.45 r0 top
DP203 "FTP_57" FTP_57 281.3,81.1 r0 top
DP251 "FTP_57" FTP_57 266.95,27.1 r90 top
DP252 "FTP_57" FTP_57 283.3,41.4 r180 top
DP253 "FTP_57" FTP_57 287.5,36.5 r180 top
DP254 "FTP_57" FTP_57 266.95,22.9 r270 top
DP255 "FTP_57" FTP_57 293.05,38.45 r90 top
DP256 "FTP_57" FTP_57 293.05,44.6 r270 top
DP257 "FTP_71" FTP_71 291.25,26.4 r0 top
DP258 "DTP815" DTP815 274.2,25.9 r0 top
DP301 "DTP915" DTP915 144.1,24.9 r180 bottom
DP302 "DTP815" DTP815 236.1,28.9 r0 top
DP303 "DTP815" DTP815 238.7,22.8 r0 top
DP304 "DTP815" DTP815 232.3,24.8 r0 top
DP401 "DTP815" DTP815 228.4,34.4 r0 top
DP402 "DTP815" DTP815 225.15,34 r90 top
DP403 "FTP_57" FTP_57 226.7,24.8 r180 top
DP404 "FTP_116" FTP_116 142.9,75.1 r0 top
DP405 "FTP_116" FTP_116 195.6,69.2 r0 top
DP406 "FTP_116" FTP_116 153.6,95.6 r0 top
DP407 "FTP_116" FTP_116 202.5,111.2 r0 top
DP451 "FTP_57" FTP_57 285.2,49.2 r0 top
DP501 "FTP_71" FTP_71 317.05,41.7 r0 top
DP502 "FTP_57" FTP_57 312.25,54.55 r90 top
DP503 "FTP_57" FTP_57 329.4,71.7 r0 top
F1 "Littelfuse_0215_phi5.5-V_A_2" Littelfuse_0215_phi5.5-V_A_2 57.05,82.45 r270 top
F401 "F_I_808****0440_LF" F_I_808****0440_LF 204.05,48.85 r270 top
HS1 "Local_BPUS15-25-A" Local_BPUS15-25-A 203.04,124 r0 top
HS2 "Local_BPUS15-25-A" Local_BPUS15-25-A 203.04,135.2 r180 top
IC1 "FTP_63" FTP_63 69.2,41.4 r0 bottom
IC51 "FTP_112" FTP_112 165.3,69 r0 top
IC52 "FTP_129" FTP_129 166.9,28.1 r90 bottom
IC101 "I8K123" I8K123 167.95,134.95 r0 top
IC102 "I8K123" I8K123 188.75,91.7 r0 top
IC151 "FTP_113" FTP_113 272.25,138.2 r270 bottom
IC201 "FTP_113" FTP_113 272.25,100.1 r270 bottom
IC251 "FTP_64" FTP_64 277.7,27.4 r270 bottom
IC301 "MM00730BKP" MM00730BKP 148.6,26.8 r0 bottom
IC302 "MM00730AKP" MM00730AKP 236.7,24.3 r0 top
IC303 "Local_4pin_SO6L-A" Local_4pin_SO6L-A 249.75,24.6 r270 top
IC304 "LocalI9K0A8" LocalI9K0A8 248.4,27.05 r270 bottom
IC401 "Local_SOIC-7-B" Local_SOIC-7-B 226.95,32.35 r0 bottom
IC402 "MM01320AKP" MM01320AKP 213.55,69.25 r0 top
IC403 "DI8G1K" DI8G1K 205.4,78.9 r0 top
IC451 "DI9G1K" DI9G1K 261.6,32.4 r270 bottom
IC501 "SOT-23-6_KA" SOT-23-6_KA 307.25,58.1 r270 top
L1 "Local_LDFW013412YV-V0E-A" Local_LDFW013412YV-V0E-A 72.643,41.97 r0 top
L2 "Local_LDFW013412YV-V0E-A" Local_LDFW013412YV-V0E-A 108.113,41.97 r0 top
L51 "FTP_118" FTP_118 111.6,123.2 r270 top
L52 "FTP_118" FTP_118 139.5,129.1 r270 top
L53 "FTP_55" FTP_55 149.8,71.8 r180 top
L54 "FTP_55" FTP_55 183.2,72.3 r90 top
L101 "Local_TMSD-Y3001" Local_TMSD-Y3001 185,130.25 r270 top
L151 "Local_CTW18A27uH" Local_CTW18A27uH 306.55,126.45 r90 top
L201 "Local_CTW18A27uH" Local_CTW18A27uH 306.55,79.35 r90 top
Q1 "MM00340BKP" MM00340BKP 113.6,87.1 r0 bottom
Q51 "RDP10020ATP" RDP10020ATP#1 148.34,80.7 r180 top
Q52 "RDP10020ATP" RDP10020ATP#1 179.54,80.7 r180 top
Q101 "RDP10020ATP" RDP10020ATP#1 154.46,151.8 r0 top
Q102 "RDP10020ATP" RDP10020ATP#1 172.36,151.8 r0 top
Q103 "RDP10020ATP" RDP10020ATP#2 176.64,106 r180 top
Q104 "RDP10020ATP" RDP10020ATP#1 195.54,106 r180 top
Q151 "Local_SOPAdvance-E-01-A" Local_SOPAdvance-E-01-A 279.9,130.5 r90 top
Q152 "Local_SOPAdvance-E-01-B" Local_SOPAdvance-E-01-B 279.9,129.4 r90 bottom
Q153 "Local_SOPAdvance-E-01-A" Local_SOPAdvance-E-01-A 279.9,151.8 r90 top
Q154 "Local_SOPAdvance-E-01-B" Local_SOPAdvance-E-01-B 279.9,151.8 r90 bottom
Q201 "Local_SOPAdvance-E-01-A" Local_SOPAdvance-E-01-A 279.9,92.4 r90 top
Q202 "Local_SOPAdvance-E-01-B" Local_SOPAdvance-E-01-B 279.9,91.3 r90 bottom
Q203 "Local_SOPAdvance-E-01-A" Local_SOPAdvance-E-01-A 279.9,113.7 r90 top
Q204 "Local_SOPAdvance-E-01-B" Local_SOPAdvance-E-01-B 279.9,113.7 r90 bottom
Q301 "MM00340AKP" MM00340AKP 242.2,23.4 r270 top
Q302 "MM00340BKP" MM00340BKP 151.7,23.3 r180 bottom
Q303 "MM00340BKP" MM00340BKP 228.5,24.5 r180 bottom
Q351 "MM00340AKP" MM00340AKP 258.45,23 r0 top
Q401 "Local_TO-220SIS-02-A" Local_TO-220SIS-02-A 226.35,41.45 r180 top
Q501 "Local_SOPAdvance-E-01-A" Local_SOPAdvance-E-01-A 326.4,62.4 r180 top
Q502 "Local_SOPAdvance-E-01-A" Local_SOPAdvance-E-01-A 333.1,62.4 r180 top
Q503 "Local_SOPAdvance-E-01-B" Local_SOPAdvance-E-01-B 333.1,62.4 r180 bottom
Q504 "Local_SOPAdvance-E-01-B" Local_SOPAdvance-E-01-B 326.4,62.4 r180 bottom
R1 "FTP_52" FTP_52 69.2,48.5 r90 bottom
R2 "FTP_52" FTP_52 69.4,34.3 r90 bottom
R3 "Local_Y5JA-330JPTL3_5-A" Local_Y5JA-330JPTL3_5-A 96.585,66.152 r180 top
R4 "KC00050BKP" KC00050BKP 116.7,86.1 r180 bottom
R5 "KC00050BKP" KC00050BKP 113.6,84.5 r0 bottom
R6 "KC00050BKP" KC00050BKP 110.8,85.4 r180 bottom
R7 "KC00050BKP" KC00050BKP 115.8,84.5 r180 bottom
R51 "KC00050AKP" KC00050AKP 174.1,65.4 r90 top
R52 "FTP_52" FTP_52 134.01,104.2 r0 bottom
R53 "KC00050BKP" KC00050BKP 136.1,100.3 r0 bottom
R54 "DR810K" DR810K 154.2,69.7 r180 top
R55 "DR810K" DR810K 154.2,71.8 r180 top
R56 "KC00050AKP" KC00050AKP 143.4,68.8 r0 top
R57 "KC00050AKP" KC00050AKP 154.4,66.3 r180 top
R58 "KC00050AKP" KC00050AKP 154.4,67.7 r180 top
R59 "KC00050AKP" KC00050AKP 161.4,64.3 r0 top
R60 "FTP_52" FTP_52 150.5,107.2 r0 bottom
R61 "KC00050BKP" KC00050BKP 153.3,103.5 r0 bottom
R62 "DR810K" DR810K 179.8,71 r0 top
R63 "DR810K" DR810K 179.8,73.3 r0 top
R64 "KC00050AKP" KC00050AKP 172.5,73.95 r0 top
R65 "KC00050AKP" KC00050AKP 179.6,67 r0 top
R66 "KC00050AKP" KC00050AKP 179.6,68.5 r0 top
R67 "KC00050AKP" KC00050AKP 174.7,63.9 r180 top
R68 "KC00050BKP" KC00050BKP 173,24.35 r180 bottom
R69 "KC00050BKP" KC00050BKP 174.85,25.4 r180 bottom
R70 "FTP_51" FTP_51 129.4,29.6 r90 bottom
R71 "FTP_51" FTP_51 131.8,26.9 r90 bottom
R72 "FTP_51" FTP_51 180,23.5 r270 bottom
R73 "KC00050BKP" KC00050BKP 177,28.3 r90 bottom
R74 "KC00050BKP" KC00050BKP 176.6,26.85 r0 bottom
R76 "KC00050BKP" KC00050BKP 172.8,32.4 r180 bottom
R77 "KC00050BKP" KC00050BKP 165.1,33 r270 bottom
R78 "KC00050BKP" KC00050BKP 163.9,33.9 r270 bottom
R79 "KC00050BKP" KC00050BKP 173.4,27.6 r90 bottom
R80 "KC00050BKP" KC00050BKP 174.5,27.6 r90 bottom
R81 "KC00050AKP" KC00050AKP 170.8,25.9 r90 top
R82 "KC00050AKP" KC00050AKP 170.8,24.1 r90 top
R83 "KC00050BKP" KC00050BKP 162.4,32.1 r270 bottom
R84 "KC00050BKP" KC00050BKP 162.4,33.9 r270 bottom
R85 "KC00050BKP" KC00050BKP 154.95,26.5 r0 bottom
R86 "KC00050BKP" KC00050BKP 160.7,25.1 r90 bottom
R87 "KC00050BKP" KC00050BKP 161.8,25.1 r90 bottom
R88 "KC00050BKP" KC00050BKP 169.8,23.4 r90 bottom
R89 "KC00050BKP" KC00050BKP 164,21.6 r90 bottom
R90 "KC00050BKP" KC00050BKP 160.3,21.7 r0 bottom
R91 "KC00050BKP" KC00050BKP 167,35.3 r0 bottom
R92 "FTP_51" FTP_51 176.1,41.4 r90 bottom
R93 "FTP_51" FTP_51 176.1,36.9 r90 bottom
R94 "FTP_51" FTP_51 176.1,32.4 r90 bottom
R95 "KC00050BKP" KC00050BKP 172.4,29.85 r270 bottom
R96 "KC00050BKP" KC00050BKP 172.8,31.3 r180 bottom
R97 "KC00050AKP" KC00050AKP 164.65,62.55 r90 top
R98 "KC00050AKP" KC00050AKP 167.3,62.55 r90 top
R101 "R9100A" R9100A 197.3,46.55 r90 bottom
R102 "R9100A" R9100A 194.35,39 r0 bottom
R103 "KC00050AKP" KC00050AKP 165.65,128.4 r270 top
R104 "KC00050AKP" KC00050AKP 162.35,128.4 r270 top
R105 "KC00050AKP" KC00050AKP 169.85,130 r270 top
R106 "KC00050BKP" KC00050BKP 177.9,139.5 r90 bottom
R107 "DR910K" DR910K 171.2,137.6 r0 bottom
R108 "DR810K" DR810K 156.6,142.35 r180 top
R109 "DR810K" DR810K 156.6,144.45 r180 top
R110 "KC00050AKP" KC00050AKP 159.9,146.25 r180 top
R111 "DR810K" DR810K 169.9,146.55 r90 top
R112 "DR810K" DR810K 172,146.55 r90 top
R113 "KC00050AKP" KC00050AKP 177.65,146.3 r180 top
R114 "KC00050AKP" KC00050AKP 186.3,86.1 r270 top
R115 "KC00050AKP" KC00050AKP 182.95,87.45 r270 top
R116 "KC00050AKP" KC00050AKP 190.85,86.9 r270 top
R117 "KC00050BKP" KC00050BKP 199.45,91.7 r90 bottom
R118 "DR910K" DR910K 192.3,94.1 r0 bottom
R119 "DR810K" DR810K 177.9,96.9 r180 top
R120 "DR810K" DR810K 177.9,99.05 r180 top
R121 "KC00050AKP" KC00050AKP 171.2,111.4 r0 top
R122 "DR810K" DR810K 197.2,99.7 r0 top
R123 "DR810K" DR810K 197.2,97.6 r0 top
R124 "KC00050BKP" KC00050BKP 190.25,111.225 r0 bottom
R151 "KC00050BKP" KC00050BKP 264.15,144.7 r0 bottom
R152 "DR910K" DR910K 281.8,136.175 r0 bottom
R153 "DR910K" DR910K 281.8,134.1 r0 bottom
R154 "KC00050BKP" KC00050BKP 285.25,133.9 r180 bottom
R155 "FTP_106" FTP_106 284.7,124.1 r180 top
R156 "DR910K" DR910K 282.1,147.2 r0 bottom
R157 "DR910K" DR910K 282.1,145.1 r0 bottom
R158 "KC00050BKP" KC00050BKP 284.8,147.05 r180 bottom
R159 "FTP_106" FTP_106 282.3,145.5 r180 top
R160 "FTP_50" FTP_50 290.5,147.305 r0 top
R161 "FTP_50" FTP_50 290.5,144.605 r0 top
R162 "R8100A" R8100A 297,149.8 r0 top
R163 "R8100A" R8100A 297,144.8 r0 top
R164 "KC00050BKP" KC00050BKP 265.35,137.55 r0 bottom
R165 "KC00050BKP" KC00050BKP 265.35,140.25 r0 bottom
R201 "KC00050BKP" KC00050BKP 264.15,106.6 r0 bottom
R202 "DR910K" DR910K 281.8,98.075 r0 bottom
R203 "DR910K" DR910K 281.8,96 r0 bottom
R204 "KC00050BKP" KC00050BKP 285.25,95.9 r180 bottom
R205 "FTP_106" FTP_106 284.7,86 r180 top
R206 "DR910K" DR910K 282.1,109.1 r0 bottom
R207 "DR910K" DR910K 282.1,107 r0 bottom
R208 "KC00050BKP" KC00050BKP 284.8,108.95 r180 bottom
R209 "FTP_106" FTP_106 282.3,107.4 r180 top
R210 "FTP_50" FTP_50 289.7,106.45 r0 top
R211 "FTP_50" FTP_50 289.7,104.105 r0 top
R212 "R8100A" R8100A 297,103.7 r0 top
R213 "R8100A" R8100A 297,98.7 r0 top
R214 "KC00050BKP" KC00050BKP 265.35,99.45 r0 bottom
R215 "KC00050BKP" KC00050BKP 265.35,102.15 r0 bottom
R251 "FTP_51" FTP_51 264.5,68.1 r270 bottom
R252 "KC00050BKP" KC00050BKP 275.225,33.5 r0 bottom
R253 "KC00050AKP" KC00050AKP 286.525,31.8 r180 top
R254 "KC00050AKP" KC00050AKP 286.525,30.7 r180 top
R255 "KC00050AKP" KC00050AKP 286.525,29.6 r180 top
R256 "KC00050AKP" KC00050AKP 286.525,28.5 r180 top
R257 "KC00050AKP" KC00050AKP 286.525,27.4 r180 top
R258 "KC00050AKP" KC00050AKP 286.525,26.3 r180 top
R259 "KC00050AKP" KC00050AKP 286.525,25.2 r180 top
R260 "KC00050BKP" KC00050BKP 270.9,33.5 r0 bottom
R261 "KC00050BKP" KC00050BKP 278.25,22 r180 bottom
R262 "KC00050BKP" KC00050BKP 279.15,20.9 r180 bottom
R263 "KC00050BKP" KC00050BKP 284.6,23.85 r0 bottom
R264 "KC00050BKP" KC00050BKP 282.7,24.5 r90 bottom
R265 "KC00050BKP" KC00050BKP 284.6,24.95 r0 bottom
R266 "KC00050BKP" KC00050BKP 272.9,24.4 r90 bottom
R267 "KC00050BKP" KC00050BKP 271.4,23.8 r0 bottom
R268 "KC00050BKP" KC00050BKP 272.25,21.6 r0 bottom
R269 "KC00050BKP" KC00050BKP 271.4,22.7 r0 bottom
R270 "KC00050AKP" KC00050AKP 270.95,22.5 r0 top
R271 "KC00050AKP" KC00050AKP 270.1,24.7 r0 top
R272 "KC00050BKP" KC00050BKP 281.9,32.6 r270 bottom
R273 "KC00050BKP" KC00050BKP 280,33.4 r0 bottom
R274 "KC00050AKP" KC00050AKP 272,24.7 r0 top
R275 "KC00050AKP" KC00050AKP 270.1,23.6 r0 top
R276 "KC00050BKP" KC00050BKP 271.4,25 r0 bottom
R277 "KC00050AKP" KC00050AKP 272.8,27.55 r90 top
R278 "KC00050AKP" KC00050AKP 274.2,29 r180 top
R279 "KC00050BKP" KC00050BKP 286.65,22.6 r90 bottom
R280 "KC00050BKP" KC00050BKP 285,22.2 r0 bottom
R281 "KC00050BKP" KC00050BKP 282.1,21.8 r90 bottom
R282 "KC00050AKP" KC00050AKP 271.6,28.4 r90 top
R283 "KC00050BKP" KC00050BKP 283.2,21.8 r90 bottom
R284 "DR810K" DR810K 269.7,28 r90 top
R285 "KC00050BKP" KC00050BKP 285.9,27.3 r180 bottom
R286 "KC00050BKP" KC00050BKP 286.4,29.85 r90 bottom
R287 "KC00050BKP" KC00050BKP 287.5,32.5 r90 bottom
R288 "KC00050BKP" KC00050BKP 288.6,31.6 r90 bottom
R289 "KC00050BKP" KC00050BKP 287.5,30.7 r90 bottom
R290 "KC00050BKP" KC00050BKP 288.6,29.8 r90 bottom
R291 "KC00050BKP" KC00050BKP 287.5,28.9 r90 bottom
R292 "DR910K" DR910K 291.1,31.8 r180 bottom
R301 "FTP_51" FTP_51 134.583,40.127 r270 bottom
R302 "FTP_51" FTP_51 136.903,37.438 r270 bottom
R303 "FTP_51" FTP_51 134.583,34.627 r270 bottom
R304 "FTP_51" FTP_51 136.883,31.927 r270 bottom
R305 "KC00050BKP" KC00050BKP 143.3,26.7 r180 bottom
R306 "KC00050BKP" KC00050BKP 143.8,28.2 r270 bottom
R307 "KC00050BKP" KC00050BKP 146.3,25.4 r270 bottom
R308 "KC00050BKP" KC00050BKP 156.1,31.9 r180 bottom
R309 "FTP_51" FTP_51 242.051,66.546 r0 bottom
R310 "FTP_51" FTP_51 244.737,69.152 r0 bottom
R311 "FTP_51" FTP_51 247.45,66.55 r0 bottom
R312 "KC00050AKP" KC00050AKP 234.25,26.3 r0 top
R313 "KC00050AKP" KC00050AKP 236.5,26.6 r0 top
R314 "KC00050AKP" KC00050AKP 240.1,25.7 r90 top
R315 "KC00050AKP" KC00050AKP 240.1,23.4 r90 top
R316 "DR810K" DR810K 242.25,25.85 r180 top
R317 "KC00050AKP" KC00050AKP 243.6,21.9 r0 top
R318 "KC00050BKP" KC00050BKP 226.7,26.4 r180 bottom
R319 "KC00050BKP" KC00050BKP 228.5,26.4 r180 bottom
R320 "KC00050AKP" KC00050AKP 142.3,24.8 r270 top
R321 "KC00050AKP" KC00050AKP 142.3,28.4 r270 top
R322 "KC00050AKP" KC00050AKP 231.439,28.916 r90 top
R323 "KC00050AKP" KC00050AKP 231.439,26.822 r90 top
R351 "KC00050AKP" KC00050AKP 256.45,23.3 r180 top
R352 "KC00050AKP" KC00050AKP 256.85,21.8 r90 top
R353 "KC00050AKP" KC00050AKP 260.55,23.65 r0 top
R354 "KC00050BKP" KC00050BKP 256.875,26.95 r180 bottom
R355 "KC00050BKP" KC00050BKP 260.8,27.4 r0 bottom
R356 "KC00050BKP" KC00050BKP 259.25,27.9 r270 bottom
R357 "KC00050BKP" KC00050BKP 256.875,25.75 r180 bottom
R358 "KC00050BKP" KC00050BKP 260.8,25.9 r0 bottom
R359 "KC00050BKP" KC00050BKP 259.25,25.7 r90 bottom
R360 "KC00050BKP" KC00050BKP 256.875,24.55 r180 bottom
R361 "KC00050BKP" KC00050BKP 260.8,23.45 r0 bottom
R362 "KC00050BKP" KC00050BKP 259.25,23.9 r270 bottom
R363 "KC00050BKP" KC00050BKP 256.875,23.4 r180 bottom
R364 "KC00050BKP" KC00050BKP 258.85,22.3 r0 bottom
R365 "KC00050BKP" KC00050BKP 256.875,22.3 r0 bottom
R401 "FTP_98" FTP_98 226.1,52.7 r180 top
R402 "DR910K" DR910K 226.15,38.55 r90 bottom
R403 "KC00050AKP" KC00050AKP 227.5,37.45 r0 top
R404 "KC00140BKP01" KC00140BKP01 218,43.75 r0 bottom
R405 "KC00140BKP01" KC00140BKP01 218,41.45 r0 bottom
R406 "KC00140BKP01" KC00140BKP01 218,39.15 r0 bottom
R407 "KC00050BKP" KC00050BKP 226.15,29 r180 bottom
R408 "KC00050BKP" KC00050BKP 231.3,36.55 r0 bottom
R409 "KC00050BKP" KC00050BKP 231.55,33.45 r90 bottom
R410 "KC00050BKP" KC00050BKP 232.65,32.55 r90 bottom
R411 "KC00050BKP" KC00050BKP 232.65,30.75 r90 bottom
R412 "KC00050BKP" KC00050BKP 231.45,30.75 r90 bottom
R413 "KC00050BKP" KC00050BKP 234.95,28.45 r0 bottom
R414 "KC00050AKP" KC00050AKP 209.45,64.85 r0 top
R415 "KC00050AKP" KC00050AKP 212.45,64.3 r0 top
R416 "KC00050AKP" KC00050AKP 205.95,71.85 r0 top
R417 "KC00050AKP" KC00050AKP 204.3,73.95 r90 top
R418 "KC00050BKP" KC00050BKP 138.8,75.1 r0 bottom
R419 "KC00050BKP" KC00050BKP 199.5,73.6 r270 bottom
R420 "KC00050BKP" KC00050BKP 157.45,95.6 r180 bottom
R421 "KC00050BKP" KC00050BKP 198.15,111.2 r0 bottom
R422 "KC00050AKP" KC00050AKP 100.7,149.1 r90 top
R423 "KC00050BKP" KC00050BKP 196.5,141.7 r180 bottom
R451 "FTP_51" FTP_51 276.45,41.35 r90 bottom
R452 "FTP_50" FTP_50 279,51.3 r270 top
R453 "KC00050BKP" KC00050BKP 266.7,33.5 r180 bottom
R454 "KC00050BKP" KC00050BKP 257.1,33.3 r180 bottom
R501 "R9100A" R9100A 332.05,84 r180 bottom
R502 "R9100A" R9100A 332.05,79.9 r180 bottom
R503 "R9100A" R9100A 332.05,75.9 r180 bottom
R504 "DR810K" DR810K 311.45,58.1 r0 top
R505 "KC00050BKP" KC00050BKP 324.55,30.392 r90 bottom
R506 "KC00050BKP" KC00050BKP 325.65,30.4 r90 bottom
RV1 "FTP_120" FTP_120 61.4,65.8 r0 top
RY1 "Local_G5PZ-1A" Local_G5PZ-1A 109.7,88.55 r270 top
T51 "FTP_94" FTP_94 140.2,91.7 r270 top
T52 "FTP_94" FTP_94 165.9,91.7 r270 top
T101 "FTP_96" FTP_96 249.3,68.45 r0 top
T151 "Local_TAM0545" Local_TAM0545 242.85,135.1 r270 top
T201 "Local_TAM0545" Local_TAM0545 242.85,97 r270 top
T401 "Local_TAM-PQ20-36-5" Local_TAM-PQ20-36-5 248.65,45.95 r270 top

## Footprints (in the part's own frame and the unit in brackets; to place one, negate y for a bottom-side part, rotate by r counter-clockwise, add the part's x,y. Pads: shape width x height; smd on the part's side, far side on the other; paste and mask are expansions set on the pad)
CUK02330ATP [mil] "KC00080BKP"
  round 70 / inner round 0 / far side round 70 hole 51.18 paste-70 mask+0: 1(0,0) 2(98.43,0)
  silkscreen extent -122,-159 220,118
CUP10050ATP [mil] "KC00080BKP"
  round 70 / inner round 0 / far side round 70 hole 51.18 paste-70 mask+0: 1(0,0) 2(98.43,0) 3(196.85,0) 4(295.28,0)
  silkscreen extent -122,-159 417,118
D9K022 [mm] "KC00080BKP"
  rect 1.36x0.55 smd paste-1.36 mask+0: A(1.025,0) C(-1.025,0)
  silkscreen extent -2.51,-0.72 2,0.72
D8101D1AKP [mm] "KC00080BKP"
  rect 0.7x0.4 smd paste-0.7 mask+0: A(-0.7,0) C(0.7,0)
  silkscreen extent -1.32,-0.55 1.82,0.55
D8101D1BKP [mm] "KC00080BKP"
  rect 0.7x0.4 smd paste-0.7 mask+0: A(0.7,0) C(-0.7,0)
  silkscreen extent -1.82,-0.55 1.32,0.55
DC835R1AKP [mm] "KC00080BKP"
  rect 1.41x3.5 smd paste-3.5 mask+0: 1(-1.95,0) 2(1.95,0)
  silkscreen extent -0.84,-1.8 0.84,1.8
DC835R1BKP [mm] "KC00080BKP"
  rect 1.41x3.5 smd paste-3.5 mask+0: 1(-1.95,0) 2(1.95,0)
  silkscreen extent -0.84,-1.8 0.84,1.8
DC845R0AKP [mm] "KC00080BKP"
  rect 4.15x1.6 smd paste-4.15 mask+0: 1(-4.375,0) 2(4.375,0)
  silkscreen extent -5.5,-5.25 7.41,7.03
DD504V [mil] "KC00080BKP"
  round 70 / inner round 0 / far side round 70 hole 51.18 paste-70 mask+0: A(0,0) C(200,0)
  silkscreen extent -122,-140 322,89
DI8G1K [mm] "KC00080BKP"
  rect 0.825x1.56 smd paste-1.56 mask+0: 1(-1.088,-1.075) 3(1.087,-1.075) 4(1.087,1.075) 5(-1.088,1.075)
  rect 0.55x1.56 smd paste-1.56 mask+0: 2(0,-1.075)
DI9G1K [mm] "KC00080BKP"
  rect 0.825x1.56 smd paste-1.56 mask+0: 1(-1.087,-1.075) 3(1.088,-1.075) 4(1.088,1.075) 5(-1.087,1.075)
  rect 0.55x1.56 smd paste-1.56 mask+0: 2(0,-1.075)
DIC8V2 [mm] "KC00080BKP"
  rect 1.25x2.049 smd paste-2.049 mask+0: 1(-2.3,-5.075) 3(2.3,-5.075)
  rect 6.5x6.85 smd paste-6.85 mask+0: 2(0,1.425)
  silkscreen extent -3.7,-3.4 3.7,3.4
DJA415 [mm] "KC00080BKP"
  round 3.175 / inner round 0 / far side round 3.175 hole 1.8 paste-3.175 mask+0: 1(0,0) 3(7.92,0)
  round 0 hole 1.8 paste-3.175 mask+0: 2(3.96,0)
  silkscreen extent -2.45,-5.5 10.37,4.3
DR810K [mm] "KC00080BKP"
  rect 0.83x1.35 smd paste-1.35 mask+0: 1(-0.8,0) 2(0.8,0)
DR910K [mm] "KC00080BKP"
  rect 0.83x1.35 smd paste-1.35 mask+0: 1(-0.8,0) 2(0.8,0)
DTP815 [mm] "KC00080BKP"
  round 1.5 smd paste-1.6 mask+0: 1(0,0)
DTP915 [mm] "KC00080BKP"
  round 1.5 smd paste-1.6 mask+0: 1(0,0)
F_I_808****0440_LF [mm] "KC00080BKP"
  round 1.5 hole 0.85 paste-1.6 mask+0: 1(-2.54,0) 2(2.54,0)
  silkscreen extent -4.45,-2.33 4.45,2.32
FTP_9 [mm] "KC00080BKP"
  round 2.6 / inner round 0 / far side round 2.6 hole 1.7 paste-2.7 mask+0: 1(-7.8,15.8) 2(-0.8,22.8) 3(6.2,15.8)
  round 0 hole 2.6 slot 4 at 90 deg unplated paste-4.25 mask+0: ""(-26.2,11.8) ""(26.2,11.8)
  round 0 hole 3.6 unplated paste-4.064 mask+0: ""(-20.05,8.75) ""(20.05,8.75)
  silkscreen extent -28.05,-4.25 28.05,24.35
FTP_13 [mm] "KC00080BKP"
  round 1.8 / inner round 0 / far side round 1.8 hole 0.9 paste-1.9 mask+0: 1(0,0) 2(5,0)
  silkscreen extent -4.2,-6.2 9.12,5.75
FTP_15 [mm] "KC00080BKP"
  rect 0.92x1.7 smd paste-1.7 mask+0: 1(-1.35,0) 2(1.35,0)
  silkscreen extent -0.59,-0.9 0.59,0.9
FTP_16 [mm] "KC00080BKP"
  rect 0.92x1.7 smd paste-1.7 mask+0: 1(1.35,0) 2(-1.35,0)
  silkscreen extent -0.59,-0.9 0.59,0.9
FTP_20 [mm] "KC00080BKP"
  rect 1.36x0.55 smd paste-1.36 mask+0: A(-1.025,0) C(1.025,0)
  silkscreen extent -2,-0.72 2.51,0.72
FTP_22 [mm] "KC00080BKP"
  rect 1.36x0.55 smd paste-1.36 mask+0: A(1.025,0) C(-1.025,0)
  silkscreen extent -2.51,-0.72 2,0.72
FTP_25 [mm] "KC00080BKP"
  rect 1.1x1.6 smd paste-1.6 mask+0: 1(-1.35,0) 2(1.35,0)
  silkscreen extent -0.5,-0.9 0.5,0.9
FTP_27 [mm] "KC00080BKP"
  rect 0.55x1.61 smd paste-1.61 mask+0: A(-0.95,-1.05) C(0,1.05) NC(0.95,-1.05)
  silkscreen extent -1.55,-0.87 1.55,0.87
FTP_31 [mm] "KC00080BKP"
  rect 0.55x1.61 smd paste-1.61 mask+0: A(0.95,1.05) C(0,-1.05) NC(-0.95,1.05)
  silkscreen extent -1.55,-0.87 1.55,0.87
FTP_32 [mm] "KC00080BKP"
  rect 0.824x0.4 smd paste-0.824 mask+0: A(1.05,0) C(-1.05,0)
  silkscreen extent -2.26,-0.67 1.76,0.67
FTP_50 [mm] "KC00080BKP"
  rect 0.92x1.7 smd paste-1.7 mask+0: 1(-1.35,0) 2(1.35,0)
  silkscreen extent -0.59,-0.9 0.59,0.9
FTP_51 [mm] "KC00080BKP"
  rect 0.92x1.7 smd paste-1.7 mask+0: 1(-1.35,0) 2(1.35,0)
  silkscreen extent -0.59,-0.9 0.59,0.9
FTP_52 [mm] "KC00080BKP"
  rect 0.895x2.6 smd paste-2.6 mask+0: 1(-1.362,0) 2(1.363,0)
  silkscreen extent -0.66,-1.35 0.66,1.35
FTP_55 [mm] "KC00080BKP"
  rect 1.17x1.7 smd paste-1.7 mask+0: 1(-1.275,0) 2(1.275,0)
FTP_57 [mm] "KC00080BKP"
  rect 3.7x2.1 smd paste-3.7 mask+0: 1(0,0)
  silkscreen extent -2.15,-1.35 2.15,1.35
FTP_63 [mm] "KC00080BKP"
  rect 0.825x1.885 smd paste-1.885 mask+0: 1(-2.042,-2.612) 4(2.043,-2.612) 5(2.043,2.613) 8(-2.042,2.613)
  rect 0.55x1.885 smd paste-1.885 mask+0: 2(-0.635,-2.612) 3(0.635,-2.612) 6(0.635,2.613) 7(-0.635,2.613)
  silkscreen extent -2.75,-3.85 2.75,1.17
FTP_64 [mm] "KC00080BKP"
  rect 0.6x1.585 smd paste-1.585 mask+0: 1(-3.675,-2.862) 12(3.675,-2.862) 13(3.675,2.863) 24(-3.675,2.863)
  rect 0.4x1.585 smd paste-1.585 mask+0: 2(-2.925,-2.862) 3(-2.275,-2.862) 4(-1.625,-2.862) 5(-0.975,-2.862) 6(-0.325,-2.862) 7(0.325,-2.862) 8(0.975,-2.862) 9(1.625,-2.862) 10(2.275,-2.862) 11(2.925,-2.862) 14(2.925,2.863) 15(2.275,2.863) 16(1.625,2.863) 17(0.975,2.863) 18(0.325,2.863) 19(-0.325,2.863) 20(-0.975,2.863) 21(-1.625,2.863) 22(-2.275,2.863) 23(-2.925,2.863)
  silkscreen extent -4.27,-3.95 3.95,1.57
FTP_65 [mm] "KC00080BKP"
  rect 0.45x0.55 smd paste-0.55 mask+0: 1(-0.425,0) 2(0.425,0)
FTP_66 [mm] "KC00080BKP"
  rect 0.45x0.55 smd paste-0.55 mask+0: 1(-0.425,0) 2(0.425,0)
FTP_68 [mm] "KC00080BKP"
  rect 0.72x0.8 smd paste-0.8 mask+0: 1(-0.64,0) 2(0.64,0)
FTP_71 [mm] "KC00080BKP"
  round 1.8 / inner round 0 / far side round 1.8 hole 1.1 paste-1.9 mask+0: 1(0,0)
  silkscreen extent -1.75,-1.75 1.75,1.75
FTP_73 [mm] "KC00080BKP"
  round 2 / inner round 0 / far side round 2 hole 1 paste-2.1 mask+0: 1(-6.25,0) 2(6.25,0)
  silkscreen extent -7.55,-4.8 7.55,4.8
FTP_75 [mm] "KC00080BKP"
  round 2.2 / inner round 0 / far side round 2.2 hole 1.1 paste-2.3 mask+0: 1(-11.25,0) 2(11.25,0)
  silkscreen extent -13.55,-9.05 13.55,9.05
FTP_81 [mm] "KC00080BKP"
  rect 1.1x2 smd paste-2 mask+0: A(-2.25,0) C(2.25,0)
  silkscreen extent -3.1,-1.3 3.6,1.3
FTP_82 [mm] "KC00080BKP"
  rect 1.1x2 smd paste-2 mask+0: A(2.25,0) C(-2.25,0)
  silkscreen extent -3.6,-1.3 3.1,1.29
FTP_86 [mm] "KC00080BKP"
  rect 1.212x1.2 smd paste-1.212 mask+0: A(1.494,0) C(-1.494,0)
  silkscreen extent -2.9,-0.9 2.4,0.9
FTP_94 [mm] "KC00080BKP"
  round 2 / inner round 0 / far side round 2 hole 1 paste-2.1 mask+0: 1(-3.6,-4.3) 2(3.6,-4.3)
  round 1.8 / inner round 0 / far side round 1.8 hole 0.9 paste-1.9 mask+0: 3(2.575,2.7) 4(-2.575,2.7)
  silkscreen extent -6.2,-6.45 6.2,6.45
FTP_96 [mm] "KC00080BKP"
  round 3.2 / inner round 0 / far side round 3.2 hole 1.6 paste-3.3 mask+0: 1(-8.89,6.35) 2(-8.89,-6.35) 6(-3.81,6.35) 7(-3.81,-6.35)
  round 2.2 / inner round 0 / far side round 2.2 hole 1.1 paste-2.3 mask+0: 3(8.89,6.35) 4(8.89,0) 5(8.89,-6.35)
  silkscreen extent -11.73,-9.19 11.73,9.19
FTP_98 [mm] "KC00080BKP"
  round 2.4 / inner round 0 / far side round 2.4 hole 1.2 paste-2.5 mask+0: 1(0,0) 2(10,0)
  silkscreen extent -3,-3 11.6,3
FTP_106 [mm] "KC00080BKP"
  rect 1.405x3.4 smd paste-3.4 mask+0: 1(-2.903,0) 2(2.902,0)
  silkscreen extent -2.1,-2 2.1,2
FTP_112 [mm] "KC00080BKP"
  rect 0.825x1.795 smd paste-1.795 mask+0: 1(-2.043,-2.557) 4(2.043,-2.557) 5(2.043,2.558) 8(-2.043,2.558)
  rect 0.55x1.795 smd paste-1.795 mask+0: 2(-0.635,-2.557) 3(0.635,-2.557) 6(0.635,2.558) 7(-0.635,2.558)
  silkscreen extent -2.76,-3.75 2.65,1.16
FTP_113 [mm] "KC00080BKP"
  rect 0.825x1.795 smd paste-1.795 mask+0: 1(2.043,2.557) 4(-2.043,2.557) 5(-2.043,-2.558) 8(2.043,-2.558)
  rect 0.55x1.795 smd paste-1.795 mask+0: 2(0.635,2.557) 3(-0.635,2.557) 6(-0.635,-2.558) 7(0.635,-2.558)
  silkscreen extent -2.65,-1.16 2.76,3.75
FTP_114 [mm] "KC00080BKP"
  round 7 / inner round 0 / far side round 7 hole 3.2 paste-7.1 mask+0: ""(0,0)
FTP_116 [mm] "KC00080BKP"
  round 3.8 / inner round 0 / far side round 3.8 hole 2.8 paste-3.9 mask+0: 1(0,0)
  silkscreen extent -2.25,-2.25 2.25,2.25
FTP_118 [mm] "KC00080BKP"
  round 3 / inner round 0 / far side round 3 hole 1.5 paste-3.1 mask+0: 1(0,-11) 2(0,11)
  silkscreen extent -15.45,-11.45 15.45,11.45
FTP_120 [mm] "KC00080BKP"
  round 2.2 / inner round 0 / far side round 2.2 hole 1.1 paste-2.3 mask+0: 1(-3.75,1.3) 2(3.75,-1.3)
  silkscreen extent -8.3,-3.65 8.3,3.65
FTP_129 [mm] "KC00080BKP"
  rect 0.6x1.46 smd paste-1.46 mask+0: 1(3.025,2.925) 10(-3.025,2.925) 11(-3.025,-2.925) 20(3.025,-2.925)
  rect 0.4x1.46 smd paste-1.46 mask+0: 2(2.275,2.925) 3(1.625,2.925) 4(0.975,2.925) 5(0.325,2.925) 6(-0.325,2.925) 7(-0.975,2.925) 8(-1.625,2.925) 9(-2.275,2.925) 12(-2.275,-2.925) 13(-1.625,-2.925) 14(-0.975,-2.925) 15(-0.325,-2.925) 16(0.325,-2.925) 17(0.975,-2.925) 18(1.625,-2.925) 19(2.275,-2.925)
  silkscreen extent -3.5,-1.69 3.62,3.96
I8K123 [mm] "KC00080BKP"
  rect 0.824x1.795 smd paste-1.795 mask+0: 1(-4.583,-2.558) 8(4.583,-2.558) 9(4.583,2.558) 16(-4.583,2.558)
  rect 0.55x1.795 smd paste-1.795 mask+0: 2(-3.175,-2.558) 3(-1.905,-2.558) 4(-0.635,-2.558) 5(0.635,-2.558) 6(1.905,-2.558) 7(3.175,-2.558) 10(3.175,2.558) 11(1.905,2.558) 12(0.635,2.558) 13(-0.635,2.558) 14(-1.905,2.558) 15(-3.175,2.558)
  silkscreen extent -5.29,-3.75 -4.17,-1.21
KC00050AKP [mm] "KC00080BKP"
  rect 0.45x0.55 smd paste-0.55 mask+0: 1(-0.425,0) 2(0.425,0)
KC00050BKP [mm] "KC00080BKP"
  rect 0.45x0.55 smd paste-0.55 mask+0: 1(-0.425,0) 2(0.425,0)
KC00060AKP [mm] "KC00080BKP"
  rect 0.8x1.25 smd paste-1.25 mask+0: 1(-0.9,0) 2(0.9,0)
KC00060BKP [mm] "KC00080BKP"
  rect 0.8x1.25 smd paste-1.25 mask+0: 1(-0.9,0) 2(0.9,0)
KC00140BKP01 [mm] "KC00080BKP"
  rect 1.15x1.8 smd paste-1.8 mask+0: 1(-1.375,0) 2(1.375,0)
  silkscreen extent -0.5,-0.9 0.5,0.9
KC01670AKP [mm] "KC00080BKP"
  rect 0.72x0.8 smd paste-0.8 mask+0: 1(-0.64,0) 2(0.64,0)
KC01670BKP [mm] "KC00080BKP"
  rect 0.72x0.8 smd paste-0.8 mask+0: 1(-0.64,0) 2(0.64,0)
Littelfuse_0215_phi5.5-V_A_2 [mm] "KC00080BKP"
  round 3 / inner round 0 / far side round 3 hole 2 paste-3.1 mask+0: 1(0,0) 2(10,0)
  silkscreen extent -3.2,-3.2 11.85,3.2
Local_4pin_SO6L-A [mm] "KC00080BKP"
  rect 0.6x1.45 smd paste-1.45 mask+0: 1(-1.27,-4.575) 3(1.27,-4.575) 4(1.27,4.575) 6(-1.27,4.575)
  silkscreen extent -2.25,-4 2.25,4
Local_7460305-A [mm] "KC00080BKP"
  round 2.2 hole 1.6 paste-2.2 mask+0: 1(-3.81,-3.81) 2(-1.27,-3.81) 3(1.27,-3.81) 4(3.81,-3.81) 5(3.81,3.81) 6(1.27,3.81) 7(-1.27,3.81) 8(-3.81,3.81)
  silkscreen extent -4.7,-2.5 4.7,2.5
Local_AL-CAP-f30-A [mm] "KC00080BKP"
  round 5.08 / inner round 0 / far side round 5.08 hole 2.6 paste-5.08 mask+0: 1(-5,0) 2(5,0)
  round 0 hole 0.8 unplated paste-1.118 mask+0: ""(0,0)
  silkscreen extent -16,-16 19.11,16
Local_BPUS15-25-A [mm] "KC00080BKP"
  round 2.7 hole 1.8 paste-2.7 mask+0: 1(0,0)
  silkscreen extent -7.7,-8.1 7.7,3.3
Local_CTW18A27uH [mm] "KC00080BKP"
  oval 7.4x2.5 / inner round 0 / far side oval 7.4x2.5 hole 1.5 slot 6.4 at 0 deg paste-7.4 mask+0: F(7,-8) S(-7,8)
  silkscreen extent -15.2,-15.2 15.2,15.2
Local_DE2E3SA222MN3AT02F [mm] "KC00080BKP"
  round 1.4 / inner round 0 / far side round 1.4 hole 0.9 paste-1.4 mask+0: 1(0,0) 2(7.5,0)
  silkscreen extent -0.75,-2.5 8.25,2.5
Local_G5PZ-1A [mm] "KC00080BKP"
  round 1.5 hole 1 paste-1.5 mask+0: 1(0,0) 4(0,7.5)
  round 1.95 hole 1.3 paste-1.95 mask+0: 2(16.5,0) 3(20,7.5)
  silkscreen extent -2.2,-1.7 22.2,9.2
Local_GSIB2580-A [mm] "KC00080BKP"
  round 2.54 / inner round 0 / far side round 2.54 hole 1.6 paste-2.54 mask+0: 1(0,0) 2(10,0) 3(17.5,0) 4(25,0)
  silkscreen extent -3.15,-5.33 28.15,3.56
Local_LDFW013412YV-V0E-A [mm] "KC00080BKP"
  round 3.15 / inner round 0 / far side round 3.15 hole 2.1 paste-3.15 mask+0: 1(-10,5) 2(10,5) 3(10,-5) 4(-10,-5)
  silkscreen extent -11.95,-17.2 11.95,17.2
Local_LONGHOLE_250-450 [mm] "KC00080BKP"
  oval 6.5x4.5 hole 2.5 slot 4.5 at 0 deg paste-6.5 mask+0: 1(0,0)
  silkscreen extent -3.5,-2.5 3.5,2.5
Local_LONGHOLE_350-700 [mm] "KC00080BKP"
  oval 9x5.5 hole 3.5 slot 7 at 0 deg paste-9 mask+0: 1(0,0)
  silkscreen extent -4.75,-3 4.75,3
Local_RDER73A104K5B1H03B-A [mm] "KC00080BKP"
  round 2.6 / inner round 0 / far side round 2.6 hole 1.3 paste-2.7 mask+0: 1(-0.02,0) 2(4.98,0)
  silkscreen extent -1.55,-2.3 6.55,2.3
Local_SOIC-7-B [mm] "KC00080BKP"
  rect 1.528x0.65 smd paste-1.528 mask+0: 1(2.711,-1.905) 2(2.711,-0.635) 3(2.711,0.635) 4(2.711,1.905) 5(-2.711,1.905) 6(-2.711,0.635) 7(-2.711,-1.905)
  silkscreen extent -1.6,-2.45 1.6,2.45
Local_SOPAdvance-E-01-A [mm] "KC00080BKP"
  rect 0.55x1.05 smd paste-1.05 mask+0: 1(-1.905,-2.975) 2(-0.635,-2.975) 3(0.635,-2.975) 4(1.905,-2.975) 5(1.905,2.975) 6(0.635,2.975) 7(-0.635,2.975) 8(-1.905,2.975)
  silkscreen extent -2.65,-3.8 2.65,3.8
Local_SOPAdvance-E-01-B [mm] "KC00080BKP"
  rect 0.55x1.05 smd paste-1.05 mask+0: 1(1.905,2.975) 2(0.635,2.975) 3(-0.635,2.975) 4(-1.905,2.975) 5(-1.905,-2.975) 6(-0.635,-2.975) 7(0.635,-2.975) 8(1.905,-2.975)
  silkscreen extent -2.65,-3.8 2.65,3.8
